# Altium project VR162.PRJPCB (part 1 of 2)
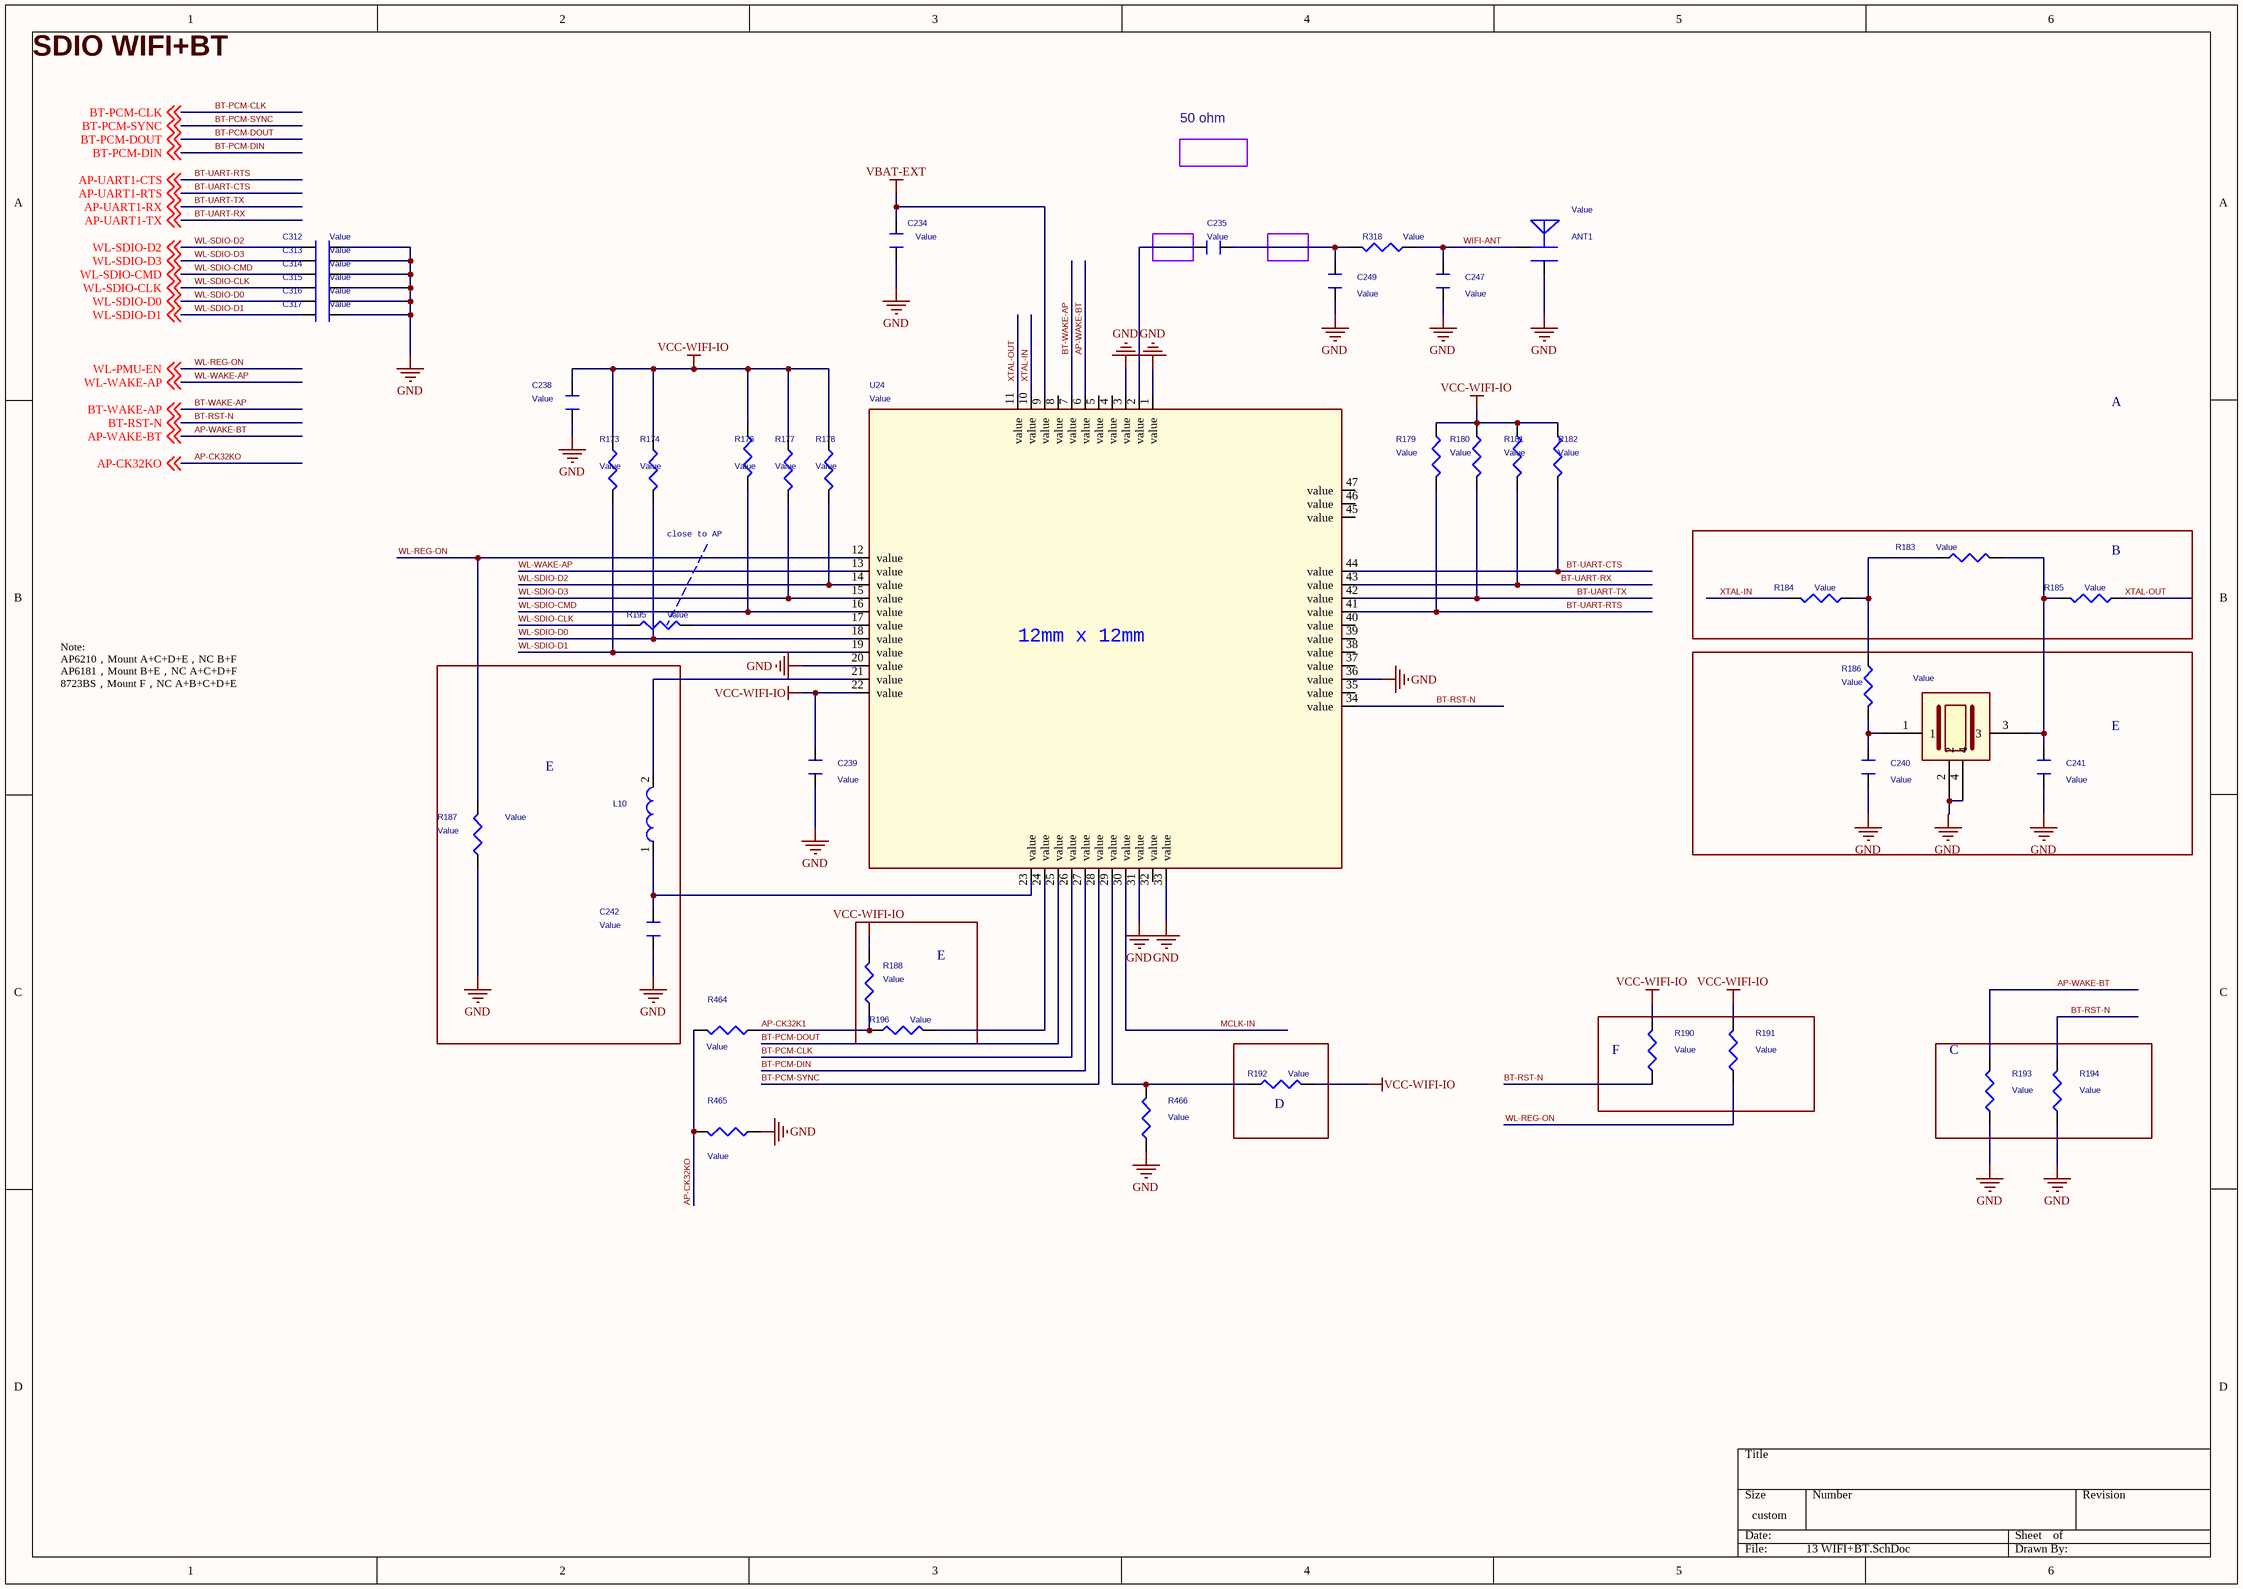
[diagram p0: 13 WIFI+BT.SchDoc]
12 sheets, 480 parts. Net scope: global (net labels, ports and power ports of the same name join across sheets).
Sheets:
  13 WIFI+BT.SchDoc
  12 CODEC.SchDoc
  11 CARD-SENSOR-VIBRATOR.SchDoc
  10 MIPI DSI.SchDoc
  08 NAND-eMMC.SchDoc
  07 POWER.SchDoc
  06 CPU.SchDoc
  05 LPDDR3_32X1.SchDoc
  03 POWER TREE.SchDoc
  14 TP.SchDoc
  09 CAMERA.SchDoc
  15 SENSOR.SchDoc

## Sheet 13 WIFI+BT.SchDoc
size 420 x 297 mm

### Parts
ANT1  Value  [CON2-WIFI-PT4]
C234  Value  [C0603]
C235  Value  [C0402]
C238  Value  [C0402]
C239  Value  [C0603]
C240  Value  [C0402]
C241  Value  [C0402]
C242  Value  [C0603]
C247  Value  [C0402]
C249  Value  [C0402]
C312  Value  [C0402]
C313  Value  [C0402]
C314  Value  [C0402]
C315  Value  [C0402]
C316  Value  [C0402]
C317  Value  [C0402]
L10  Value  [L3518]
R173  Value  [R0402]
R174  Value  [R0402]
R176  Value  [R0402]
R177  Value  [R0402]
R178  Value  [R0402]
R179  Value  [R0402]
R180  Value  [R0402]
R181  Value  [R0402]
R182  Value  [R0402]
R183  Value  [R0402]
R184  Value  [R0402]
R185  Value  [R0402]
R186  Value  [R0402]
R187  Value  [R0402]
R188  Value  [R0402]
R190  Value  [R0402]
R191  Value  [R0402]
R192  Value  [R0402]
R193  Value  [R0402]
R194  Value  [R0402]
R195  Value  [R0402]
R196  Value  [R0402]
R318  Value  [R0402]
R464  Value  [R0402]
R465  Value  [R0402]
R466  Value  [R0402]
U24  Value  [QFN44P0_90B12_00X12_00H1_50]
Y1  Value  [XTAL-1.6X1.2]

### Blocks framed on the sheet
B: R183-R185
E: C242 L10 R187
E: C240 C241 R186 Y1
E: R188 R196
D: R192
F: R190 R191
C: R193 R194

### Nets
GND: ANT1.2 C234.1 C238.1 C239.2 C240.2 C241.2 C242.2 C247.2 C249.2 C312.1 C313.1 C314.1 C315.1 C316.1 C317.1 R187.1 R193.1 R194.1 R465.1 R466.1 U24.1(value) U24.3(value) U24.20(value) U24.31(value) U24.33(value) U24.36(value) Y1.2 Y1.4
VBAT-EXT: C234.2 U24.9(value)  [project net BB-VBAT]
VCC-WIFI-IO: C238.2 C239.1 R173.1 R174.1 R176.1 R177.1 R178.1 R179.1 R180.1 R181.1 R182.1 R188.2 R190.2 R191.2 R192.2 U24.22(value)  [project net DLDO1]
AP-CK32K1: R188.1 R196.1 R464.1
AP-CK32KO: R464.2 R465.2 ; off-sheet AP-CK32KO
AP-WAKE-BT: R193.2 U24.6(value) ; off-sheet AP-WAKE-BT
BT-PCM-CLK: U24.26(value) ; off-sheet BT-PCM-CLK
BT-PCM-DIN: U24.27(value) ; off-sheet BT-PCM-DIN
BT-PCM-DOUT: U24.25(value) ; off-sheet BT-PCM-DOUT
BT-PCM-SYNC: U24.28(value) ; off-sheet BT-PCM-SYNC
BT-RST-N: R190.1 R194.2 U24.34(value) ; off-sheet BT-RST-N
BT-UART-CTS: R182.2 U24.44(value) ; off-sheet AP-UART1-RTS  [also labelled AP-UART1-RTS]
BT-UART-RTS: R179.2 U24.41(value) ; off-sheet AP-UART1-CTS  [also labelled AP-UART1-CTS]
BT-UART-RX: R181.2 U24.43(value) ; off-sheet AP-UART1-TX  [also labelled AP-UART1-TX]
BT-UART-TX: R180.2 U24.42(value) ; off-sheet AP-UART1-RX  [also labelled AP-UART1-RX]
BT-WAKE-AP: U24.7(value) ; off-sheet BT-WAKE-AP
MCLK-IN: U24.30(value)
WIFI-ANT: ANT1.1 C247.1 R318.1
WL-REG-ON: R187.2 R191.1 U24.12(value) ; off-sheet WL-PMU-EN  [also labelled WL-PMU-EN]
WL-SDIO-CLK: C315.2 R195.1 ; off-sheet WL-SDIO-CLK
WL-SDIO-CMD: C314.2 R176.2 U24.16(value) ; off-sheet WL-SDIO-CMD
WL-SDIO-D0: C316.2 R174.2 U24.18(value) ; off-sheet WL-SDIO-D0
WL-SDIO-D1: C317.2 R173.2 U24.19(value) ; off-sheet WL-SDIO-D1
WL-SDIO-D2: C312.2 R178.2 U24.14(value) ; off-sheet WL-SDIO-D2
WL-SDIO-D3: C313.2 R177.2 U24.15(value) ; off-sheet WL-SDIO-D3
WL-WAKE-AP: U24.13(value) ; off-sheet WL-WAKE-AP
XTAL-IN: R184.2 U24.10(value)
XTAL-OUT: R185.1 U24.11(value)
NetC235_1: C235.1 C249.1 R318.2
NetC235_2: C235.2 U24.2(value)
NetC240_1: C240.1 R186.2 Y1.1
NetC241_1: C241.1 R183.2 R185.2 Y1.3
NetC242_1: C242.1 L10.1 U24.23(value)
NetL10_2: L10.2 U24.21(value)
NetR183_1: R183.1 R184.1 R186.1
NetR192_1: R192.1 R466.2 U24.29(value)
NetR195_2: R195.2 U24.17(value)
NetR196_2: R196.2 U24.24(value)

Not connected (* = marked no-connect by the designer): U24 4(value) 5(value) 8(value) 32(value) 35(value) 37(value) 38(value) 39(value) 40(value) 45(value) 46(value) 47(value)

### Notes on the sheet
- SDIO WIFI+BT
- 50 ohm
- A
- close to AP
- Note:
  AP6210，Mount A+C+D+E，NC B+F
  AP6181，Mount B+E，NC A+C+D+F
  8723BS，Mount F，NC A+B+C+D+E

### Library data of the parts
ANT1 = T_POINT_R_0
C234 C235 C238-C242 C247 C249 C312-C317 = CAPACITOR_0_Dup3: PAGE: 2
L10 = INDUCTOR_Dup2
R173 R174 R176-R183 R186 R187 R190-R196 R318 R466 = R_Dup2
R184 R185 R188 R464 R465 = R_Dup1
U24 = AP6493_0: ORCAD_LIB: MODULE; QVL: AMPAK; Device: APSERIES
Y1 = Crystal_0

## Sheet 12 CODEC.SchDoc
size 420 x 297 mm
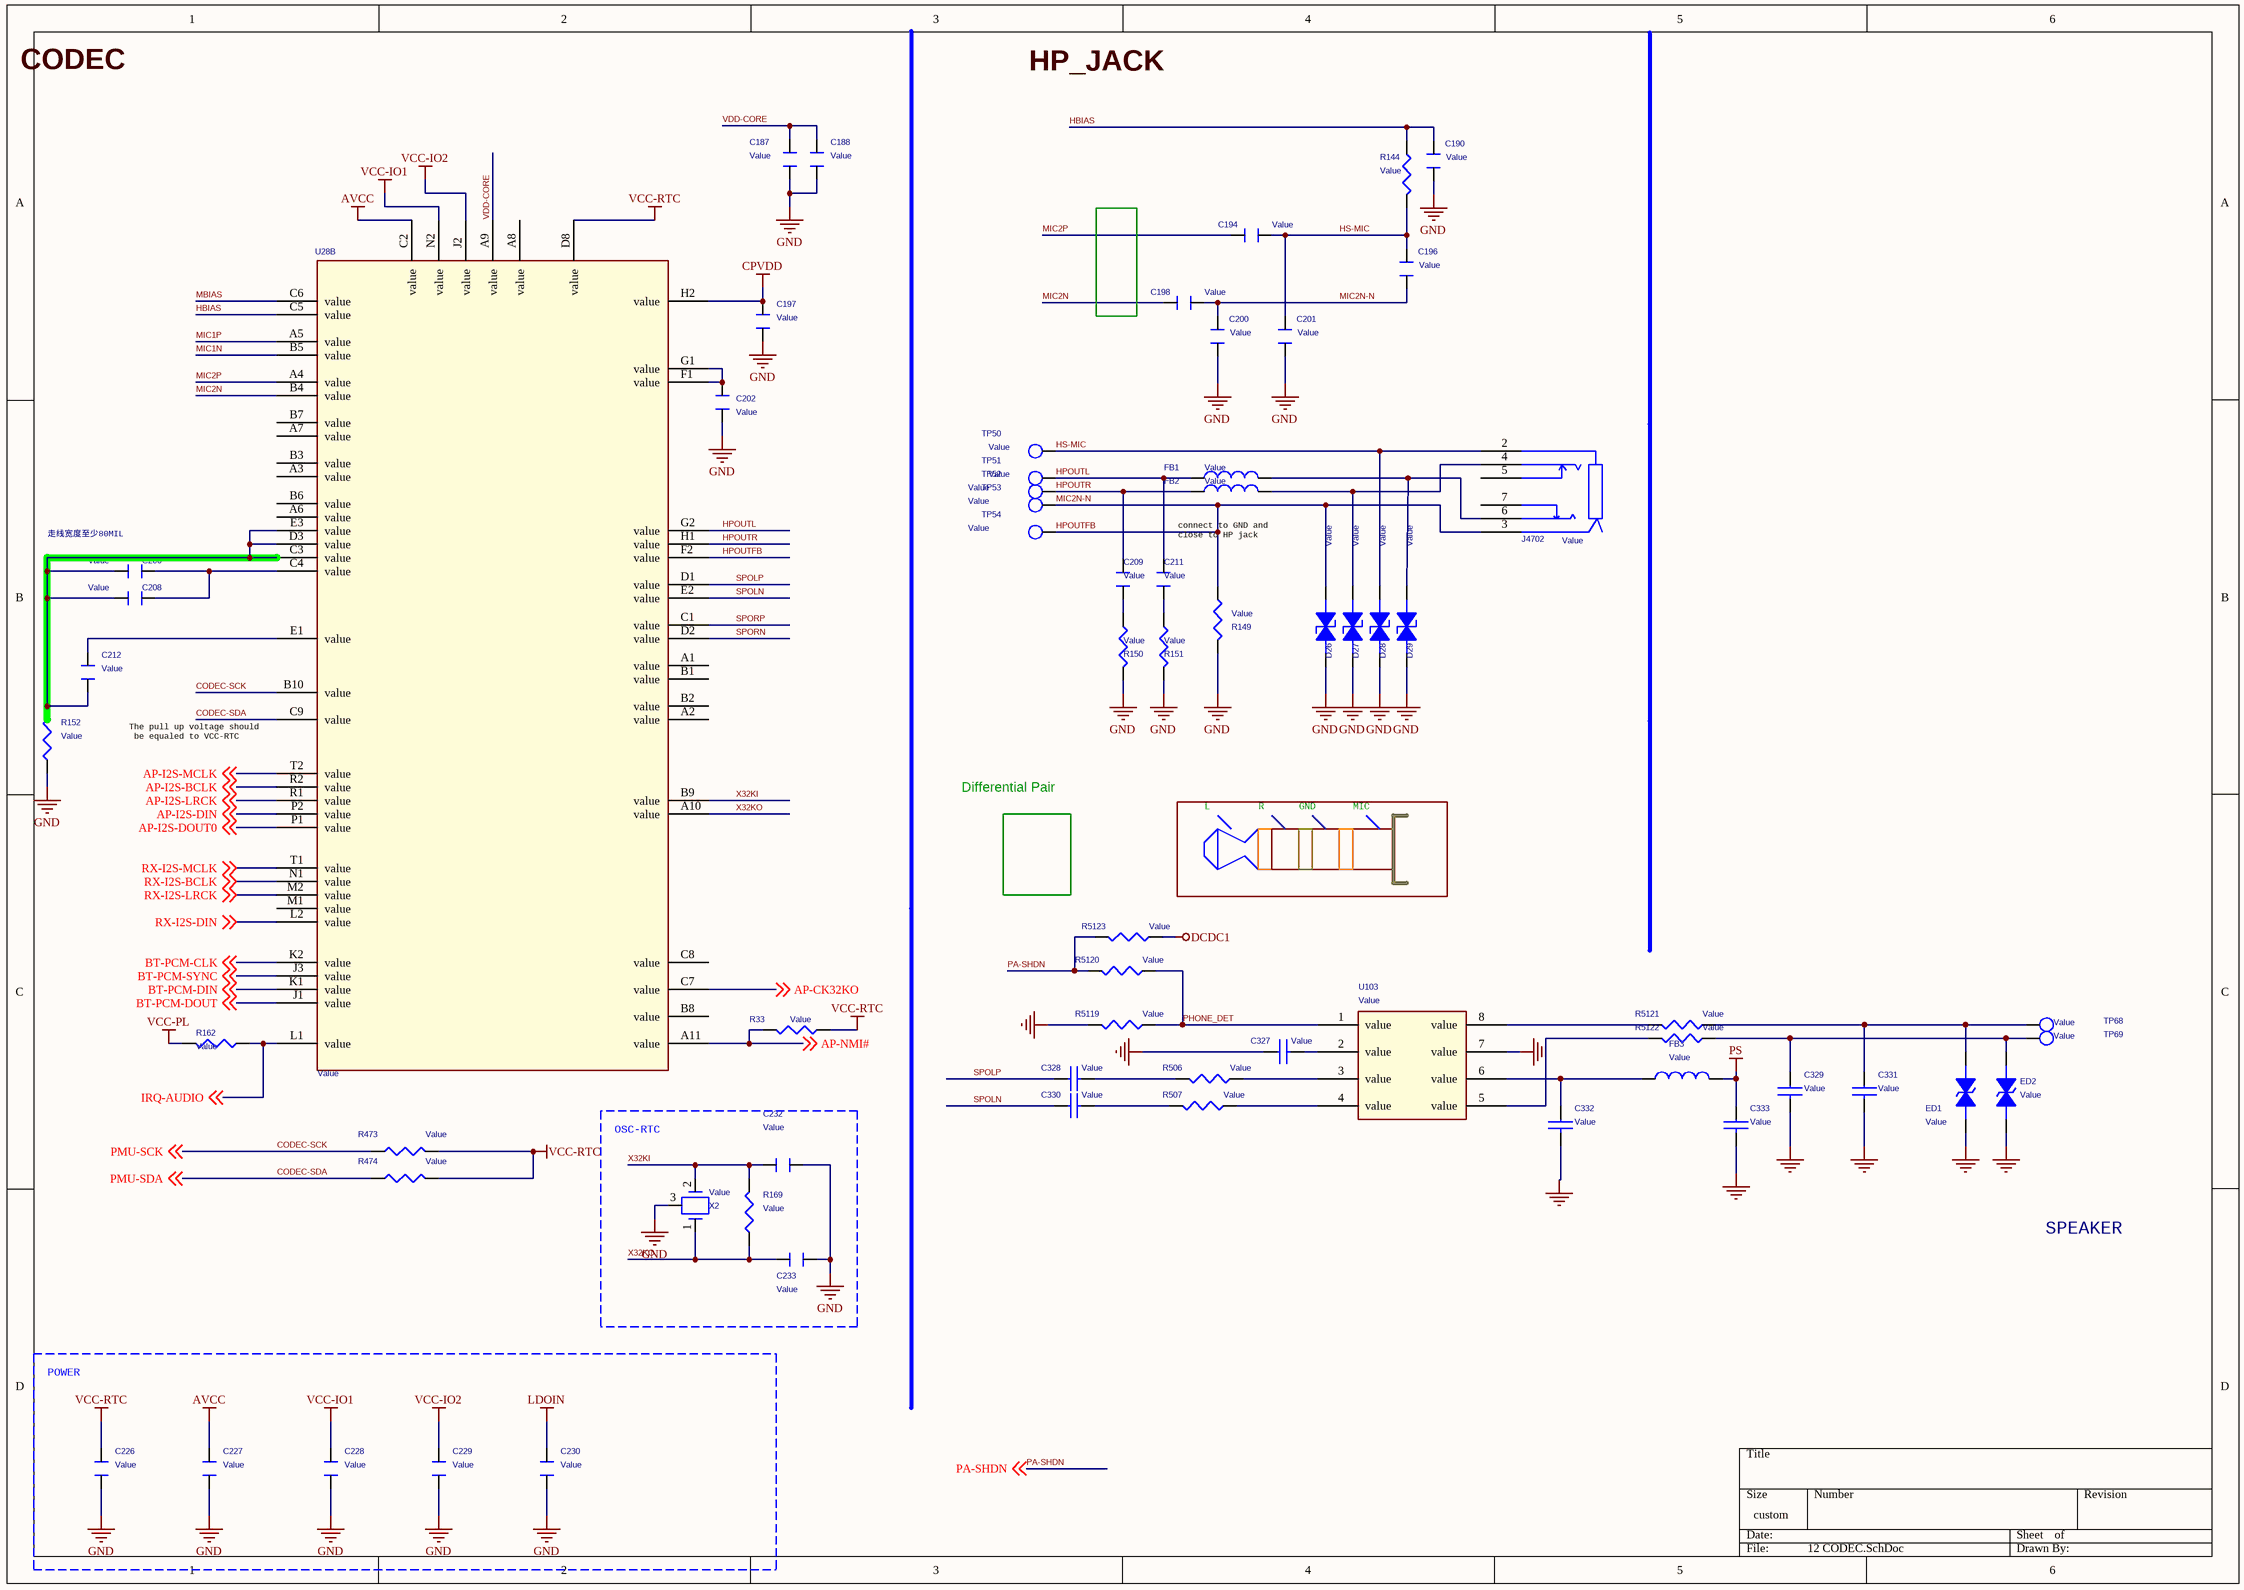
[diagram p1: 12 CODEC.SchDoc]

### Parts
C187  Value  [C0603]
C188  Value  [C0402]
C190  Value  [C0603]
C194  Value  [C0402]
C196  Value  [C0402]
C197  Value  [C0402]
C198  Value  [C0402]
C200  Value  [C0402]
C201  Value  [C0402]
C202  Value  [C0603]
C206  Value  [C0603]
C208  Value  [C0402]
C209  Value  [C0402]
C211  Value  [C0402]
C212  Value  [C0603]
C226  Value  [C0402]
C227  Value  [C0402]
C228  Value  [C0402]
C229  Value  [C0402]
C230  Value  [C0402]
C232  Value  [C0402]
C233  Value  [C0402]
C327  Value  [C0402]
C328  Value  [C0402]
C329  Value  [C0402]
C330  Value  [C0402]
C331  Value  [C0402]
C332  Value  [C0402]
C333  Value  [C0402]
D26  Value  [C0402]
D27  Value  [C0402]
D28  Value  [C0402]
D29  Value  [C0402]
ED1  Value  [E0402N]
ED2  Value  [E0402N]
FB1  Value  [L0402]
FB2  Value  [L0402]
FB3  Value  [L0603]
J4702  Value  [HP_JACK]
R33  Value  [R0402]
R144  Value  [R0402]
R149  Value  [0805]
R150  Value  [0805]
R151  Value  [0805]
R152  Value  [R0402]
R162  Value  [R0402]
R169  Value  [R0402]
R473  Value  [R0402]
R474  Value  [R0402]
R506  Value  [R0402]
R507  Value  [R0402]
R5119  Value  [R0402]
R5120  Value  [R0402]
R5121  Value  [R0402]
R5122  Value  [R0402]
R5123  Value  [R0402]
TP50  Value  [TP_SMD]
TP51  Value  [TP_SMD]
TP52  Value  [TP_SMD]
TP53  Value  [TP_SMD]
TP54  Value  [TP_SMD]
TP68  Value  [TP_SMD]
TP69  Value  [TP_SMD]
U28  Value  [BGA218_P0_65B11X11]  (part B of 4)
U103  Value  [MSOP8-PT1-27A]
X2  Value  [XCOL-3]

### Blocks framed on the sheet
OSC-RTC: C232 C233 R169 X2
POWER: C226-C230

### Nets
AVCC: C227.2 R162.2 U28.C2(value)  [also labelled VCC-PL]  [project net ALDO3]
CPVDD: C197.1 C230.2 U28.H2(value)  [also labelled LDOIN]  [project net ALDO2]
DCDC1: C228.2 R5123.1 U28.N2(value)  [also labelled VCC-IO1]
GND: C187.1 C188.1 C190.1 C197.2 C200.1 C201.1 C202.2 C226.1 C227.1 C228.1 C229.1 C230.1 C232.1 C233.1 C327.1 C329.2 C331.2 C332.2 C333.2 D26.2(CATHODE) D27.2(CATHODE) D28.2(CATHODE) D29.2(CATHODE) ED1.2 ED2.2 R149.1 R150.1 R151.1 R152.1 R5119.2 U103.7(value) X2.3(Shield)
PS: C333.1 FB3.1
VCC-IO2: C229.2 U28.J2(value)  [project net DLDO1]
VCC-RTC: C226.2 R33.1 R473.1 R474.1 U28.D8(value)
AP-CK32KO: U28.C7(value) ; off-sheet AP-CK32KO
AP-I2S-BCLK: U28.R2(value) ; off-sheet AP-I2S-BCLK
AP-I2S-DIN: U28.P2(value) ; off-sheet AP-I2S-DIN
AP-I2S-DOUT0: U28.P1(value) ; off-sheet AP-I2S-DOUT0
AP-I2S-LRCK: U28.R1(value) ; off-sheet AP-I2S-LRCK
AP-I2S-MCLK: U28.T2(value) ; off-sheet AP-I2S-MCLK
AP-NMI#: R33.2 U28.A11(value) ; off-sheet AP-NMI#
BT-PCM-CLK: U28.K2(value) ; off-sheet BT-PCM-CLK
BT-PCM-DIN: U28.K1(value) ; off-sheet BT-PCM-DIN
BT-PCM-DOUT: U28.J1(value) ; off-sheet BT-PCM-DOUT
BT-PCM-SYNC: U28.J3(value) ; off-sheet BT-PCM-SYNC
CODEC-SCK: R473.2 U28.B10(value) ; off-sheet PMU-SCK  [also labelled PMU-SCK]
CODEC-SDA: R474.2 U28.C9(value) ; off-sheet PMU-SDA  [also labelled PMU-SDA]
HBIAS: C190.2 R144.2 U28.C5(value)
HPOUTFB: C196.1 C198.2 C200.2 D26.1(ANODE) J4702.3 R149.2 TP53.1(TP) TP54.1(TP) U28.F2(value)  [also labelled MIC2N-N]
HPOUTL: C211.2 FB1.1 TP51.1(TP) U28.G2(value)
HPOUTR: C209.2 FB2.1 TP52.1(TP) U28.H1(value)
HS-MIC: C194.2 C196.2 C201.2 D28.1(ANODE) J4702.2(G) R144.1 TP50.1(TP)
IRQ-AUDIO: R162.1 U28.L1(value) ; off-sheet IRQ-AUDIO
MBIAS: U28.C6(value)
MIC1N: U28.B5(value)
MIC1P: U28.A5(value)
MIC2N: C198.1 U28.B4(value)
MIC2P: C194.1 U28.A4(value)
PA-SHDN: R5120.2 R5123.2 ; off-sheet PA-SHDN
PHONE_DET: R5119.1 R5120.1 U103.1(value)
RX-I2S-BCLK: U28.N1(value) ; off-sheet RX-I2S-BCLK
RX-I2S-DIN: U28.L2(value) ; off-sheet RX-I2S-DIN
RX-I2S-LRCK: U28.M2(value) ; off-sheet RX-I2S-LRCK
RX-I2S-MCLK: U28.T1(value) ; off-sheet RX-I2S-MCLK
SPOLN: C330.1 U28.E2(value)
SPOLP: C328.1 U28.D1(value)
SPORN: U28.D2(value)
SPORP: U28.C1(value)
VDD-CORE: C187.2 C188.2 U28.A9(value)
X32KI: C232.2 R169.2 U28.B9(value) X2.2
X32KO: C233.2 R169.1 U28.A10(value) X2.1
NetC202_1: C202.1 U28.F1(value) U28.G1(value)
NetC206_1: C206.1 C208.1 C212.2 R152.2 U28.C3(value) U28.D3(value) U28.E3(value)
NetC206_2: C206.2 C208.2 U28.C4(value)
NetC209_1: C209.1 R150.2
NetC211_1: C211.1 R151.2
NetC212_1: C212.1 U28.E1(value)
NetC327_2: C327.2 U103.2(value)
NetC328_2: C328.2 R506.2
NetC329_1: C329.1 ED2.1 R5122.1 TP69.1(TP)
NetC330_2: C330.2 R507.2
NetC331_1: C331.1 ED1.1 R5121.1 TP68.1(TP)
NetC332_1: C332.1 FB3.2 U103.6(value)
NetD27_1: D27.1(ANODE) FB2.2 J4702.4
NetD29_1: D29.1(ANODE) FB1.2 J4702.6
NetR506_1: R506.1 U103.3(value)
NetR507_1: R507.1 U103.4(value)
NetR5121_2: R5121.2 U103.8(value)
NetR5122_2: R5122.2 U103.5(value)

Not connected (* = marked no-connect by the designer): J4702 5 7; U28 A1(value) A2(value) A3(value) A6(value) A7(value) A8(value) B1(value) B2(value) B3(value) B6(value) B7(value) B8(value) C8(value) M1(value)

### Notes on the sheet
- CODEC
- HP_JACK
- connect to GND and
  close to HP jack
- 走线宽度至少80MIL
- (near U28) The pull up voltage should
  be equaled to VCC-RTC
- Differential Pair
- L
- R
- GND
- MIC
- SPEAKER

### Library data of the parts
C187 C232 C233 = CAPACITOR_0_Dup3: PAGE: 2
C188 C209 C211 C226-C230 = CAPACITOR_0_Dup3
C190 C194 C196 C198 C200 C201 = CAPACITOR: PAGE: 2
C197 C202 C206 C208 C212 = CAPACITOR_0_Dup2: PAGE: 1
C327 = CAP NP_Dup1: RoHS CHIP CAP 1uF +10/-10% X5R; BOM_VALUE: 0; BOM_TYPE: 30
C328 C329 C331 C333 = CAP NP_Dup1: RoHS CHIP CAP 0.1uF +10/-10% X7R; BOM_TYPE: 30; BOM_VALUE: 0
C330 = CAP NP_Dup1: RoHS CHIP CAP 0.1uF +10/-10% X7R; BOM_VALUE: 0; BOM_TYPE: 30
C332 = CAP NP_Dup1: RoHS CHIP CAP 10uF +10/-10% X5R; BOM_VALUE: 0; MARK: 106; ROOM: USB+5V; BOM_TYPE: 30
D26-D29 = 1_1.5KE100A: 1ST PART DESCRIPTION: WILL ESD9B5V Bidirection ESD Protection
ED1 ED2 = DIODE BI-DIR TRIG: NC/ESD Component,5V,30P,SMD,0402; BOM_TYPE: 43; BOM_VALUE: 0
FB1 FB2 = INDUCTOR_2
FB3 = INDUCTOR: ROHS CHIP RES 0 Ohm 1/16W +/-5%; BOM_TYPE: 20; BOM_VALUE: 0
J4702 = HP_JACK_0
R33 R152 R162 R169 = R_Dup1
R144 R473 R474 = R_Dup2
R149-R151 = R1 0805_Dup1
R506 = RESISTOR_Dup1: ROHS CHIP RES 30K 1/16W +/-5%; BOM_VALUE: 0; BOM_TYPE: 20
R507 R5121 R5122 = RESISTOR_Dup1: ROHS CHIP RES 62K 1/16W +/-5%; BOM_VALUE: 0; BOM_TYPE: 20
R5119 = RESISTOR_Dup1: ROHS CHIP RES 1M 1/16W +/-5%; BOM_TYPE: 20; BOM_VALUE: 0
R5120 R5123 = RESISTOR_Dup1: ROHS CHIP RES 100K 1/16W +/-5%
TP50-TP54 TP68 TP69 = T_POINT_R
U28 = AW1660_70_BGA218_1
U103 = LM4990_0: Class D Audio AMP; BOM_TYPE: 10; BOM_VALUE: 8
X2 = CRYSTAL_XCOL-3

## Sheet 11 CARD-SENSOR-VIBRATOR.SchDoc
size 420 x 297 mm
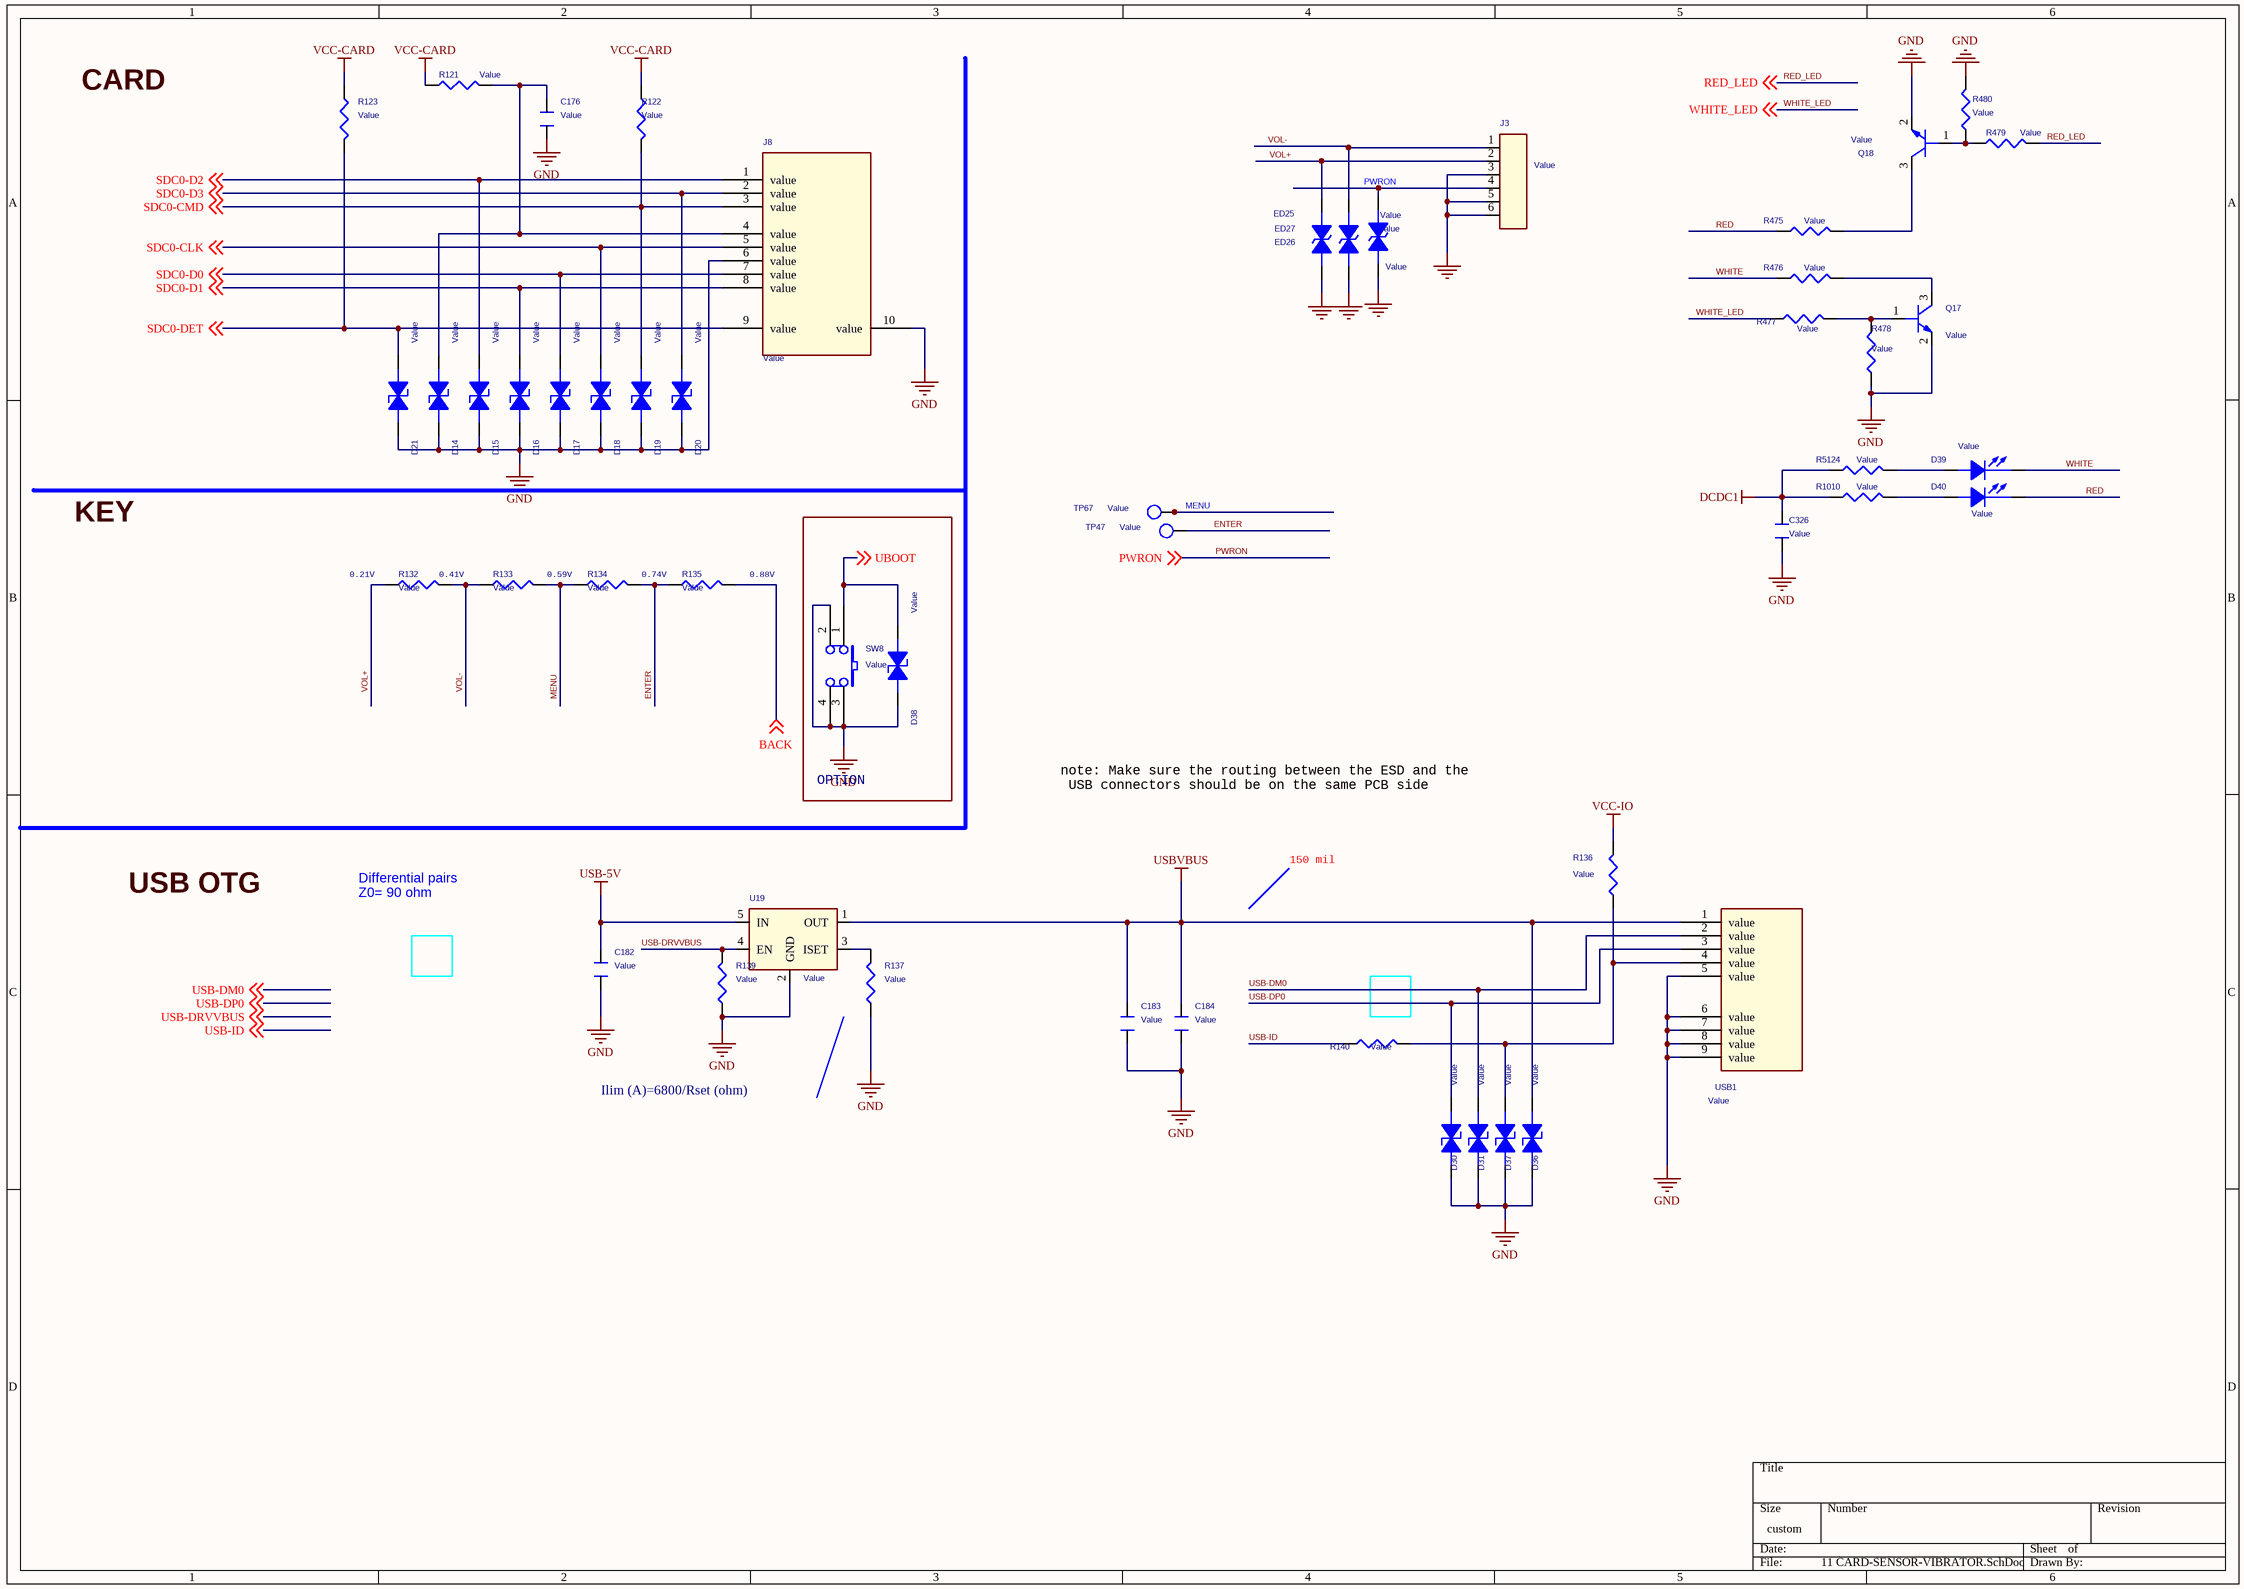
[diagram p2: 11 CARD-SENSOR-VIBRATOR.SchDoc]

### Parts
C176  Value  [C0603]
C182  Value  [C0402]
C183  Value  [C0402]
C184  Value  [C0603]
C326  Value  [C0402]
D14  Value  [C0402]
D15  Value  [C0402]
D16  Value  [C0402]
D17  Value  [C0402]
D18  Value  [C0402]
D19  Value  [C0402]
D20  Value  [C0402]
D21  Value  [C0402]
D30  Value  [C0402]
D31  Value  [C0402]
D36  Value  [C0402]
D37  Value  [C0402]
D38  Value  [C0402]
D39  Value  [LED0603]
D40  Value  [LED0603]
ED25  Value  [R0402]
ED26  Value  [R0402]
ED27  Value  [R0402]
J3  Value  [FPC4-PT1_25-3_8X10H4_6B]
J8  Value  [MICROSD_SLOT]
Q17  Value  [SOT-23]
Q18  Value  [SOT-23]
R121  Value  [R0603]
R122  Value  [R0402]
R123  Value  [R0402]
R132  Value  [0805]
R133  Value  [0805]
R134  Value  [0805]
R135  Value  [0805]
R136  Value  [R0402]
R137  Value  [R0402]
R139  Value  [R0402]
R140  Value  [R0402]
R475  Value  [R0402]
R476  Value  [R0402]
R477  Value  [R0402]
R478  Value  [R0402]
R479  Value  [R0402]
R480  Value  [R0402]
R1010  Value  [R0402]
R5124  Value  [R0402]
SW8  Value  [SW4]
TP47  Value  [TP_SMD]
TP67  Value  [TP_SMD]
U19  Value  [SOT23-6]
USB1  Value  [USB_MINI_AB]

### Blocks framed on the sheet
OPTION: D38 SW8

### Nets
DCDC1: C326.2 R121.1 R122.1 R123.1 R136.2 R1010.1 R5124.1  [also labelled VCC-CARD, VCC-IO]
GND: C176.1 C182.1 C183.1 C184.1 C326.1 D14.2(CATHODE) D15.2(CATHODE) D16.2(CATHODE) D17.2(CATHODE) D18.2(CATHODE) D19.2(CATHODE) D20.2(CATHODE) D21.2(CATHODE) D30.2(CATHODE) D31.2(CATHODE) D36.2(CATHODE) D37.2(CATHODE) D38.2(CATHODE) ED25.2 ED26.2 ED27.2 J3.3 J3.5 J3.6 J8.6(value) J8.10(value) Q17.2(E) Q18.2(E) R137.1 R139.1 R478.1 R480.2 SW8.2 SW8.3 SW8.4 U19.2(GND) USB1.5(value) USB1.6(value) USB1.7(value) USB1.8(value) USB1.9(value)
USB-5V: C182.2 U19.5(IN)
USBVBUS: C183.2 C184.2 D36.1(ANODE) U19.1(OUT) USB1.1(value)
BACK: R135.2 ; off-sheet BACK
ENTER: R134.2 R135.1 TP47.1(TP)
MENU: R133.2 R134.1 TP67.1(TP)
PWRON: ED25.1 J3.4 ; off-sheet PWRON
RED: D40.2(CATHODE) R475.1
RED_LED: R479.2 ; off-sheet RED_LED
SDC0-CLK: D18.1(ANODE) J8.5(value) ; off-sheet SDC0-CLK
SDC0-CMD: D19.1(ANODE) J8.3(value) R122.2 ; off-sheet SDC0-CMD
SDC0-D0: D17.1(ANODE) J8.7(value) ; off-sheet SDC0-D0
SDC0-D1: D16.1(ANODE) J8.8(value) ; off-sheet SDC0-D1
SDC0-D2: D15.1(ANODE) J8.1(value) ; off-sheet SDC0-D2
SDC0-D3: D20.1(ANODE) J8.2(value) ; off-sheet SDC0-D3
SDC0-DET: D21.1(ANODE) J8.9(value) R123.2 ; off-sheet SDC0-DET
UBOOT: D38.1(ANODE) SW8.1 ; off-sheet UBOOT
USB-DM0: D31.1(ANODE) USB1.2(value) ; off-sheet USB-DM0
USB-DP0: D30.1(ANODE) USB1.3(value) ; off-sheet USB-DP0
USB-DRVVBUS: R139.2 U19.4(EN) ; off-sheet USB-DRVVBUS
USB-ID: R140.1 ; off-sheet USB-ID
VOL+: ED27.1 J3.2 R132.1
VOL-: ED26.1 J3.1 R132.2 R133.1
WHITE: D39.2(CATHODE) R476.1
WHITE_LED: R477.1 ; off-sheet WHITE_LED
NetC176_2: C176.2 D14.1(ANODE) J8.4(value) R121.2
NetD37_1: D37.1(ANODE) R136.1 R140.2 USB1.4(value)
NetD39_1: D39.1(ANODE) R5124.2
NetD40_1: D40.1(ANODE) R1010.2
NetQ17_1: Q17.1(B) R477.2 R478.2
NetQ17_3: Q17.3(C) R476.2
NetQ18_1: Q18.1(B) R479.1 R480.1
NetQ18_3: Q18.3(C) R475.2
NetR137_2: R137.2 U19.3(ISET)

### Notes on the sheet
- CARD
- KEY
- (near R132) 0.21V
- (near R132) 0.41V
- 0.59V
- 0.74V
- (near R135) 0.88V
- note: Make sure the routing between the ESD and the
  USB connectors should be on the same PCB side
- Differential pairs
  Z0= 90 ohm
- 150 mil
- USB OTG
- Ilim (A)=6800/Rset (ohm)

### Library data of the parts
C176 = CAPACITOR_0_Dup3: PAGE: 2
C182-C184 C326 = CAPACITOR
D14-D21 D30 D31 D36-D38 = 1_1.5KE100A: as D26 on sheet 12 CODEC
D39 D40 = LED_0: PAGE: 1
ED25-ED27 = DIODE BI-DIR TRIG: ESD
J3 = CON2_2
J8 = SDMMC SLOT_0
Q17 Q18 = NPN
R121-R123 R140 R475-R480 R1010 R5124 = R_Dup2
R132-R135 = R1 0805_Dup2
R136 R137 R139 = R_Dup1
SW8 = SW_PUSH: SDTSourceLibName: C:\WIND95\TEMP\6200.LIB
TP47 TP67 = T_POINT_R
U19 = RT9266PE_2
USB1 = USB_MINI_SOCKET_5: USB JACK ROHS

## Sheet 10 MIPI DSI.SchDoc
size 449 x 350 mm
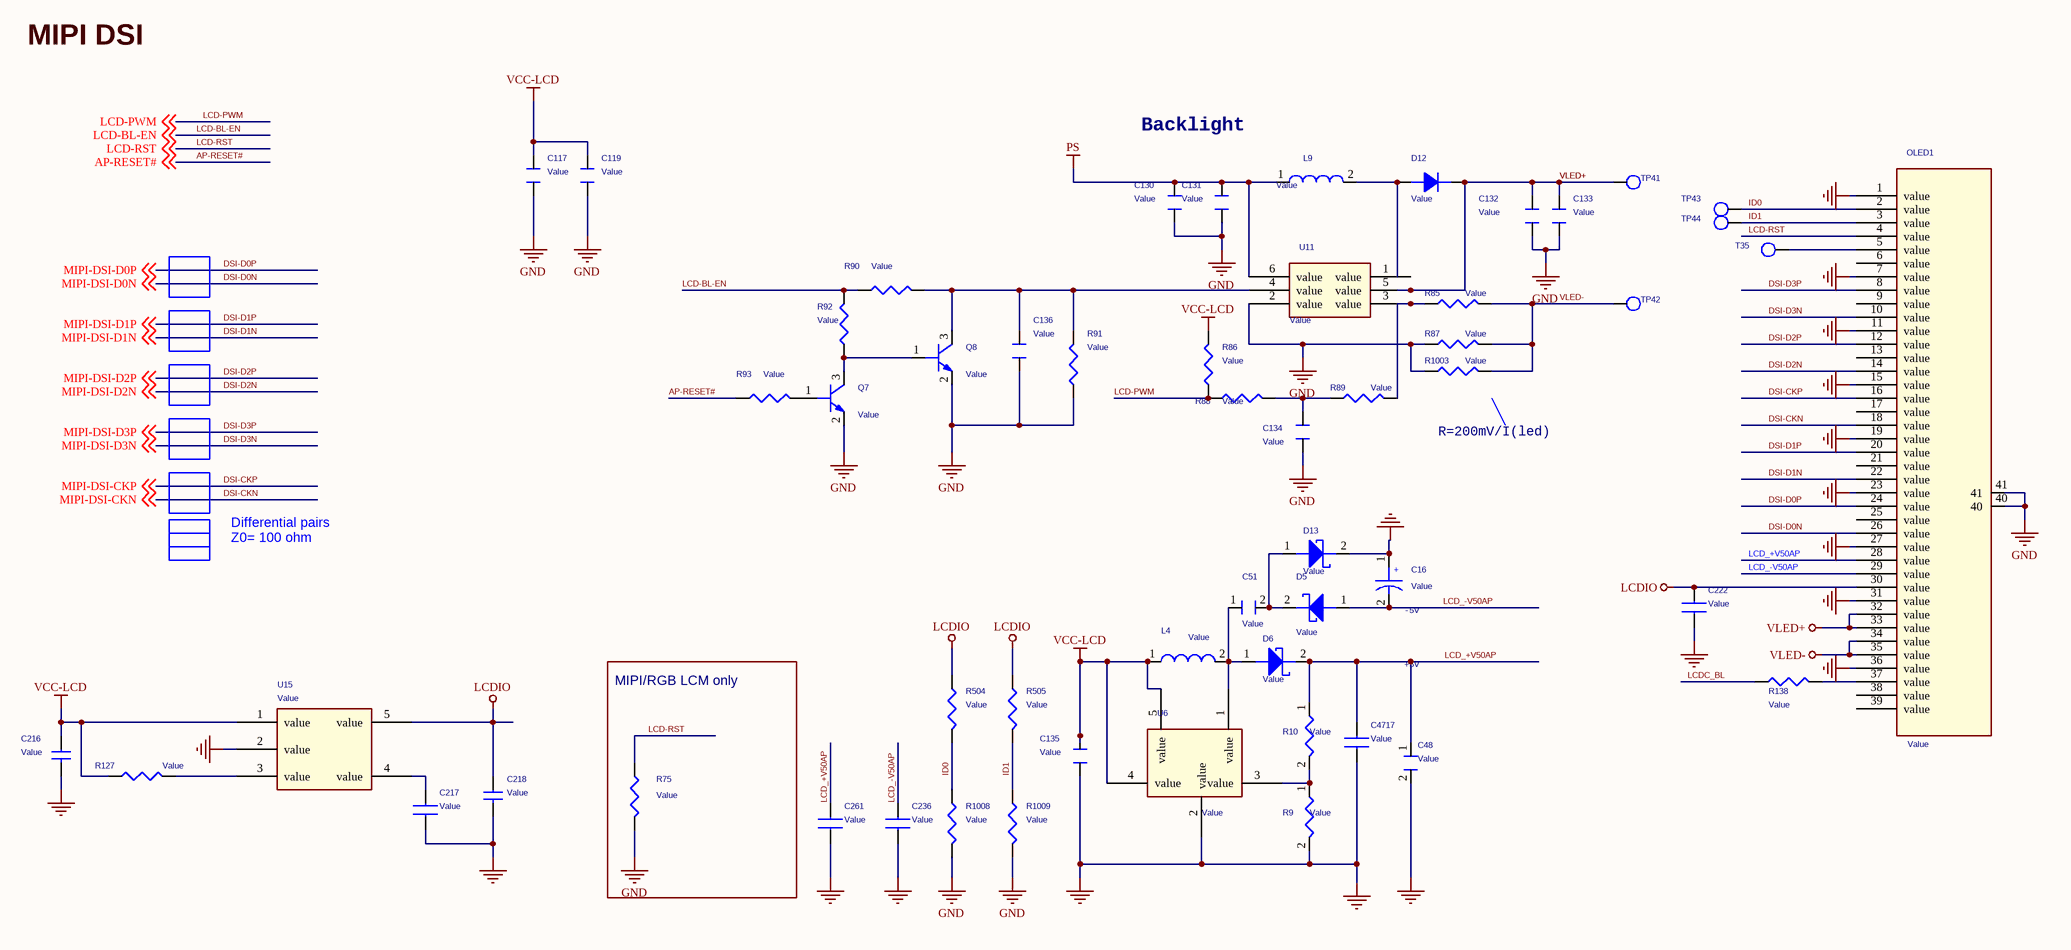
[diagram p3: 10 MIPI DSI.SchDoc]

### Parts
C16  Value  [1210]
C48  Value  [C0603]
C51  Value  [C0603]
C117  Value  [C0603]
C119  Value  [C0402]
C130  Value  [C0603]
C131  Value  [C0402]
C132  Value  [C0805]
C133  Value  [C0402]
C134  Value  [C0402]
C135  Value  [C0603]
C136  Value  [C0402]
C216  Value  [C0603]
C217  Value  [C0603]
C218  Value  [C0603]
C222  Value  [C0603]
C236  Value  [C0603]
C261  Value  [C0603]
C4717  Value  [C0603]
D5  Value  [SOD123]
D6  Value  [SOD123]
D12  Value  [SOD123]
D13  Value  [SOD123]
L4  Value  [CD32]
L9  Value  [L4018]
OLED1  Value  [40P_MIPI]
Q7  Value  [SOT-23]
Q8  Value  [SOT-23]
R9  Value  [0805]
R10  Value  [0805]
R75  Value  [R0402]
R85  Value  [R0402]
R86  Value  [R0402]
R87  Value  [R0603]
R88  Value  [R0402]
R89  Value  [R0402]
R90  Value  [R0402]
R91  Value  [R0402]
R92  Value  [R0402]
R93  Value  [R0402]
R127  Value  [R0402]
R138  Value  [R0402]
R504  Value  [R0402]
R505  Value  [R0402]
R1003  Value  [R0603]
R1008  Value  [R0402]
R1009  Value  [R0402]
T35  Value  [TEST]  (value not drawn)
TP41  Value  [TP_SMD]  (value not drawn)
TP42  Value  [TP_SMD]  (value not drawn)
TP43  Value  [TP_SMD]  (value not drawn)
TP44  Value  [TP_SMD]  (value not drawn)
U6  Value  [sot23-5]
U11  Value  [SOT23-6]
U15  Value  [SOT23_5H14A]

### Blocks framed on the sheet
MIPI/RGB LCM only: R75

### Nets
GND: C16.1 C48.2 C117.1 C119.1 C130.1 C131.1 C132.1 C133.1 C134.1 C135.1 C136.1 C216.2 C217.2 C218.2 C222.2 C236.2 C261.2 C4717.2 D13.2 OLED1.1(value) OLED1.7(value) OLED1.11(value) OLED1.15(value) OLED1.19(value) OLED1.23(value) OLED1.27(value) OLED1.31(value) OLED1.36(value) OLED1.40 OLED1.41 Q7.2(E) Q8.2(E) R9.2 R75.2 R87.2 R91.1 R1003.2 R1008.2 R1009.2 U6.2(value) U11.2(value) U15.2(value)
LCDIO: C218.1 C222.1 OLED1.30(value) R504.1 R505.1 U15.5(value)
PS: C130.2 C131.2 L9.1 U11.6(value)
VCC-LCD: C117.2 C119.2 C135.2 C216.1 L4.1 R86.2 R127.1 U6.4(value) U6.5(value) U15.1(value)  [project net DC1-SW]
VLED+: C132.2 C133.2 D12.2 OLED1.32(value) OLED1.33(value) TP41.1(TP) U11.5(value)
VLED-: OLED1.34(value) OLED1.35(value) R85.2 R87.1 R1003.1 TP42.1(TP)
AP-RESET#: R93.1 ; off-sheet AP-RESET#
DSI-CKN: OLED1.18(value) ; off-sheet MIPI-DSI-CKN  [also labelled MIPI-DSI-CKN]
DSI-CKP: OLED1.16(value) ; off-sheet MIPI-DSI-CKP  [also labelled MIPI-DSI-CKP]
DSI-D0N: OLED1.26(value) ; off-sheet MIPI-DSI-D0N  [also labelled MIPI-DSI-D0N]
DSI-D0P: OLED1.24(value) ; off-sheet MIPI-DSI-D0P  [also labelled MIPI-DSI-D0P]
DSI-D1N: OLED1.22(value) ; off-sheet MIPI-DSI-D1N  [also labelled MIPI-DSI-D1N]
DSI-D1P: OLED1.20(value) ; off-sheet MIPI-DSI-D1P  [also labelled MIPI-DSI-D1P]
DSI-D2N: OLED1.14(value) ; off-sheet MIPI-DSI-D2N  [also labelled MIPI-DSI-D2N]
DSI-D2P: OLED1.12(value) ; off-sheet MIPI-DSI-D2P  [also labelled MIPI-DSI-D2P]
DSI-D3N: OLED1.10(value) ; off-sheet MIPI-DSI-D3N  [also labelled MIPI-DSI-D3N]
DSI-D3P: OLED1.8(value) ; off-sheet MIPI-DSI-D3P  [also labelled MIPI-DSI-D3P]
ID0: OLED1.2(value) R504.2 R1008.1 TP43.1(TP)
ID1: OLED1.3(value) R505.2 R1009.1 TP44.1(TP)
LCD-BL-EN: R90.1 R92.2 ; off-sheet LCD-BL-EN
LCD-PWM: R86.1 R88.1 ; off-sheet LCD-PWM
LCD-RST: OLED1.4(value) R75.1 ; off-sheet LCD-RST
LCD_+V50AP: C48.1 C261.1 C4717.1 D6.2 OLED1.28(value) R10.1
LCD_-V50AP: C16.2 C236.1 D5.1 OLED1.29(value)
LCDC_BL: R138.1
NetC51_1: C51.1 D6.1 L4.2 U6.1(value)
NetC51_2: C51.2 D5.2 D13.1
NetC134_2: C134.2 R88.2 R89.1
NetC136_2: C136.2 Q8.3(C) R90.2 R91.2 U11.4(value)
NetC217_1: C217.1 U15.4(value)
NetD12_1: D12.1 L9.2
NetOLED1_5: OLED1.5(value) T35.1
NetOLED1_37: OLED1.37(value) R138.2
NetQ7_1: Q7.1(B) R93.2
NetQ7_3: Q7.3(C) Q8.1(B) R92.1
NetR9_1: R9.1 R10.2 U6.3(value)
NetR85_1: R85.1 R89.2 U11.3(value)
NetR127_2: R127.2 U15.3(value)

Not connected (* = marked no-connect by the designer): OLED1 6(value) 9(value) 13(value) 17(value) 21(value) 25(value) 38(value) 39(value); U11 1(value)

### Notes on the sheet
- MIPI DSI
- Backlight
- R=200mV/I(led)
- Differential pairs
  Z0= 100 ohm
- (near C16) -5v
- +5v

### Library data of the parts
C16 = CAP_P_1210
C48 C51 = CAPACITOR_3: PAGE: 3
C117 C119 C130-C136 = CAPACITOR_0: PAGE: 2
C216 C218 = SMALL CAP: 贴片电容
C217 C222 C236 C261 C4717 = CAP NP
D5 D6 D13 = DIODE SCHOTTKY_0: PAGE: 3
D12 = D_0: Allegro PCB Footprint: d2513A
L4 = INDUCTOR_Dup1: PAGE: 3
L9 = INDUCTOR_Dup3: RoHS Power Inductor 22uH 300mA H<1.8MM,CD32
OLED1 = 40P_MIPI_0
Q7 Q8 = NPN
R9 R10 = RESISTOR_3: PAGE: 3
R75 R85-R93 R504 R505 R1003 R1008 R1009 = RESISTOR_Dup2
R127 R138 = RES 1B_Dup1: ROHS CHIP RES 4.7K 1/16W 5%
T35 = TESTPOINT1: TEST
TP41-TP44 = T_POINT_R
U6 = SP6646_0: PAGE: 3
U11 = AP3031_0
U15 = LDO-PT5108/RT9013_0

## Sheet 08 NAND-eMMC.SchDoc
size 420 x 297 mm
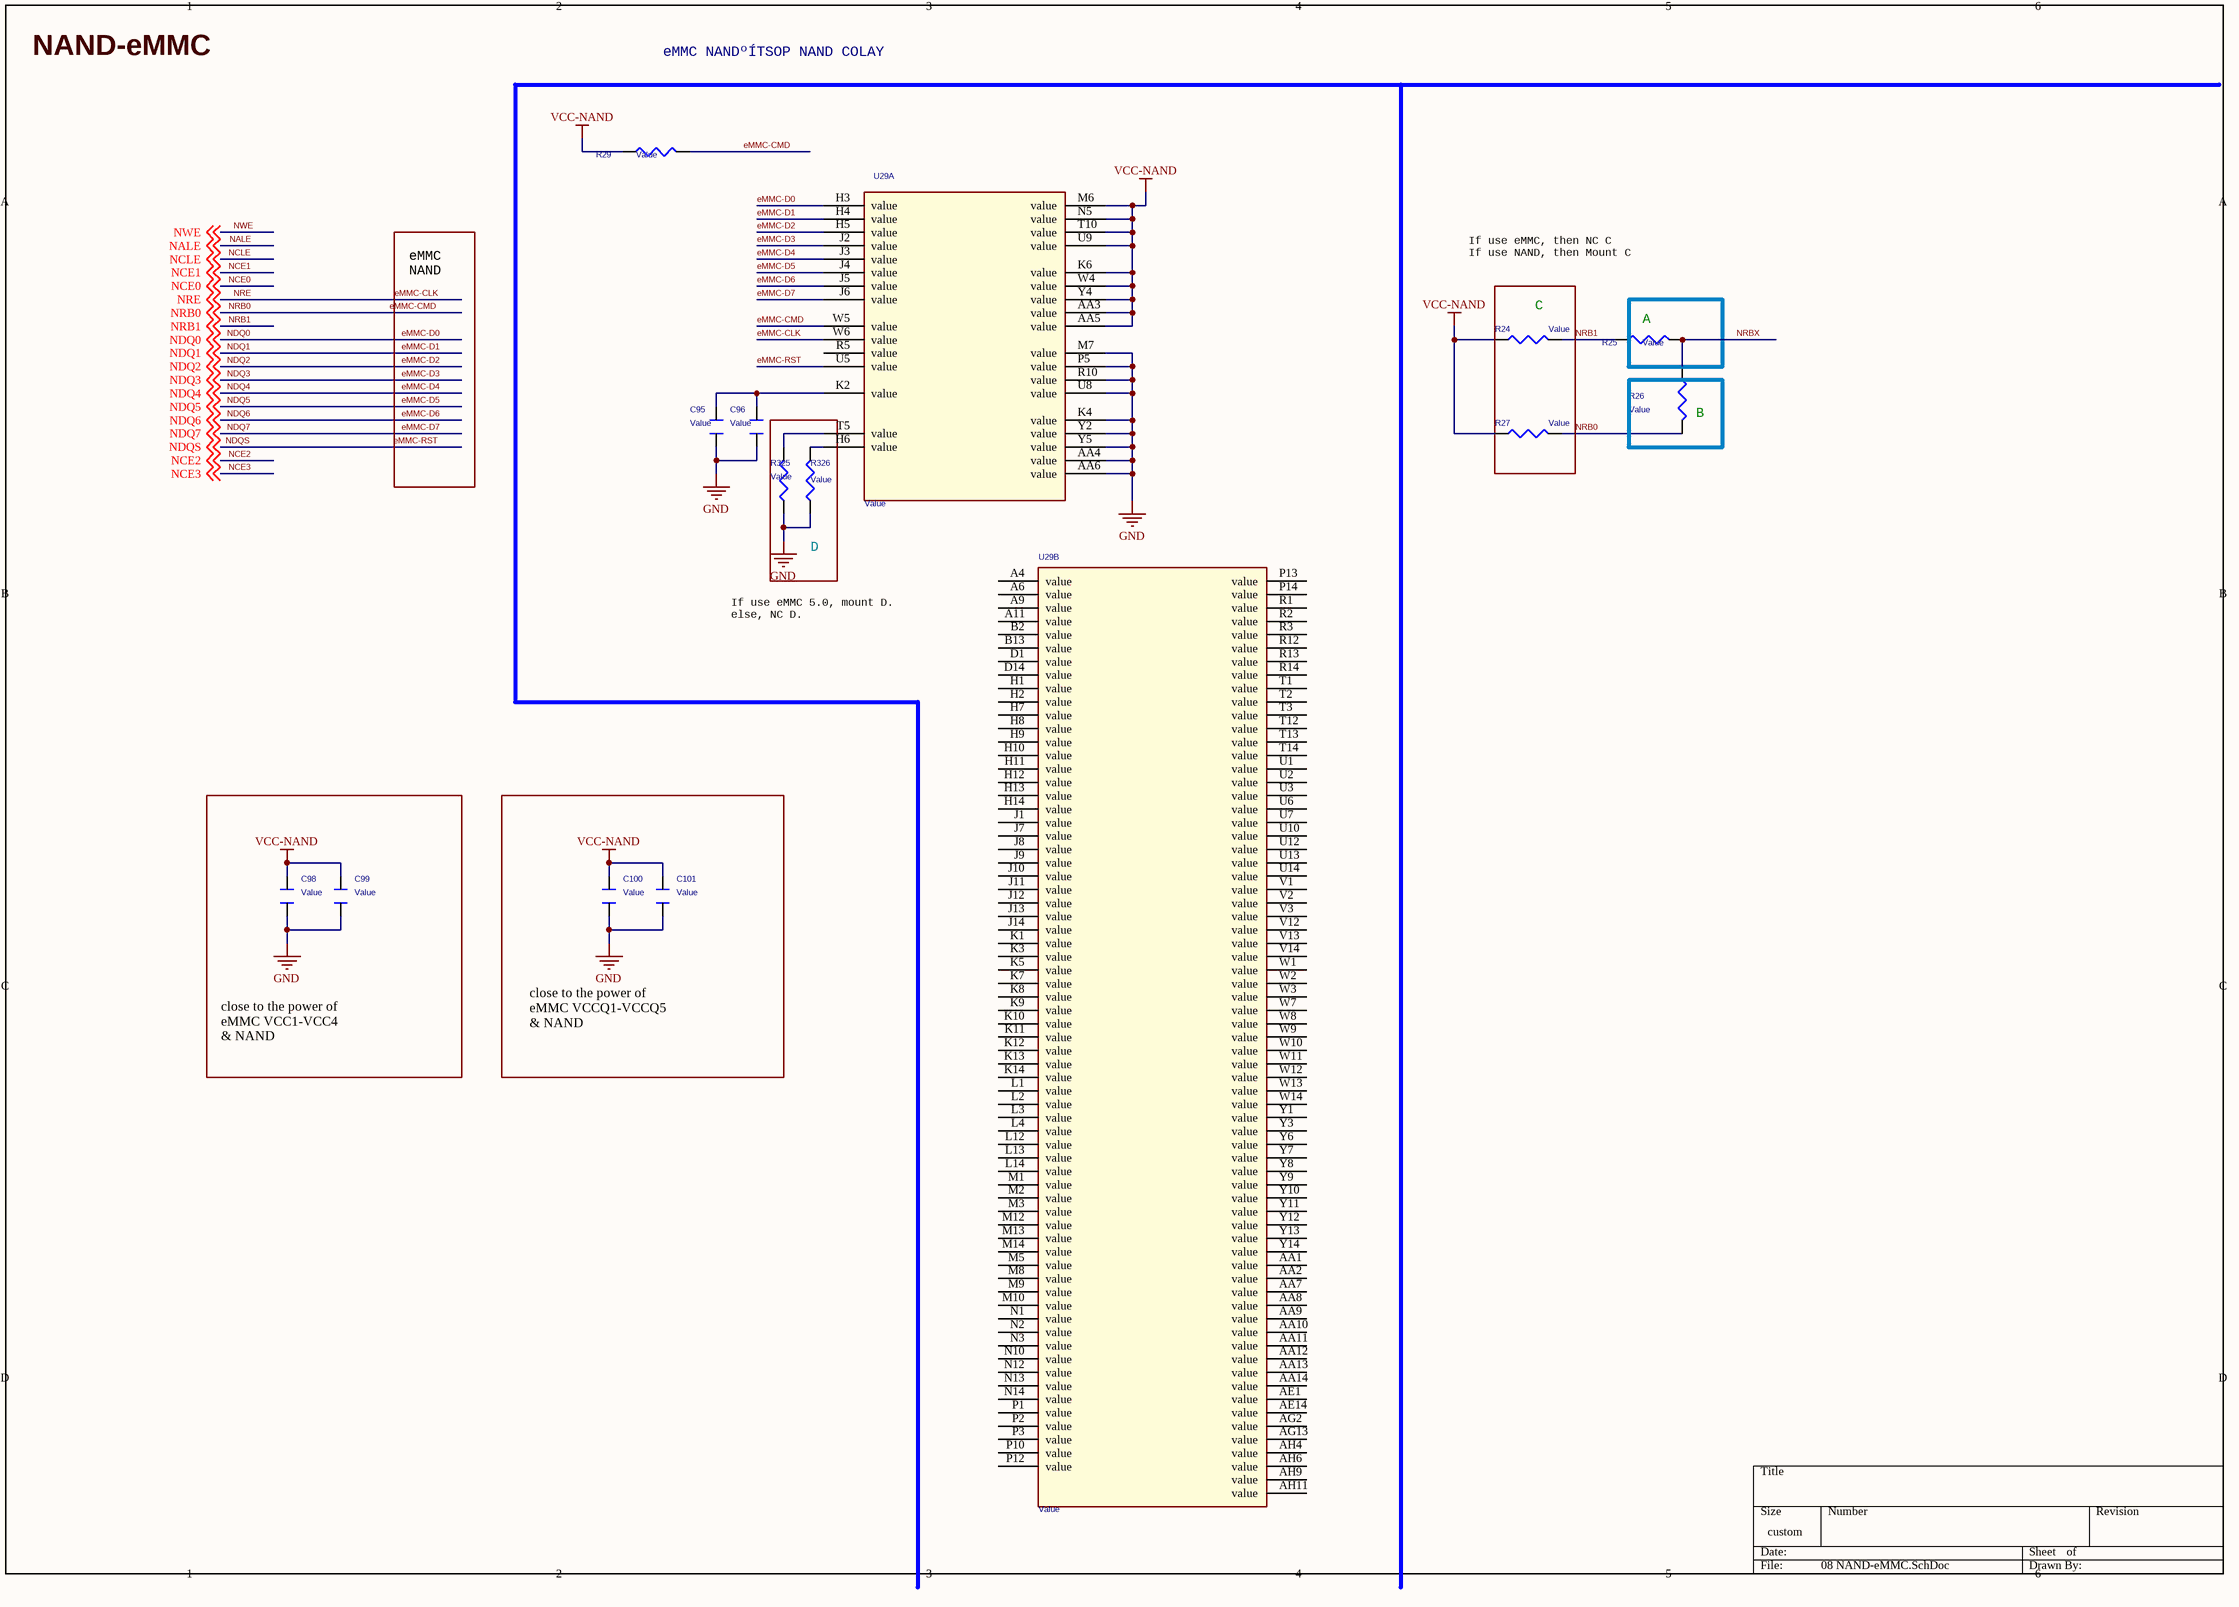
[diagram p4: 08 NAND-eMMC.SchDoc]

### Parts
C95  Value  [C0402]
C96  Value  [C0402]
C98  Value  [C0402]
C99  Value  [C0402]
C100  Value  [C0402]
C101  Value  [C0402]
R24  Value  [R0402]
R25  Value  [R0402]
R26  Value  [R0402]
R27  Value  [R0402]
R29  Value  [R0402]
R325  Value  [R0402]
R326  Value  [R0402]
U29  Value  [BGA169P0_50B12_00X16_00H1_00]  (parts A,B of 2)

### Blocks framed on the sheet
C: R24 R27
A: R25
D: R325 R326
B: R26

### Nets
GND: C95.1 C96.1 C98.1 C99.1 C100.1 C101.1 R325.1 R326.1 U29.AA4(value) U29.AA6(value) U29.K4(value) U29.M7(value) U29.P5(value) U29.R10(value) U29.U8(value) U29.Y2(value) U29.Y5(value)
VCC-NAND: C98.2 C99.2 C100.2 C101.2 R24.1 R27.1 R29.1 U29.AA3(value) U29.AA5(value) U29.K6(value) U29.M6(value) U29.N5(value) U29.T10(value) U29.U9(value) U29.W4(value) U29.Y4(value)  [project net DCDC1]
eMMC-CLK: U29.W6(value) ; off-sheet NRE  [also labelled NRE]
eMMC-CMD: R26.2 R27.2 R29.2 U29.W5(value) ; off-sheet NRB0  [also labelled NRB0]
eMMC-D0: U29.H3(value) ; off-sheet NDQ0  [also labelled NDQ0]
eMMC-D1: U29.H4(value) ; off-sheet NDQ1  [also labelled NDQ1]
eMMC-D2: U29.H5(value) ; off-sheet NDQ2  [also labelled NDQ2]
eMMC-D3: U29.J2(value) ; off-sheet NDQ3  [also labelled NDQ3]
eMMC-D4: U29.J3(value) ; off-sheet NDQ4  [also labelled NDQ4]
eMMC-D5: U29.J4(value) ; off-sheet NDQ5  [also labelled NDQ5]
eMMC-D6: U29.J5(value) ; off-sheet NDQ6  [also labelled NDQ6]
eMMC-D7: U29.J6(value) ; off-sheet NDQ7  [also labelled NDQ7]
eMMC-RST: U29.U5(value) ; off-sheet NDQS  [also labelled NDQS]
NRB1: R24.2 R25.1 ; off-sheet NRB1
NRBX: R25.2 R26.1
NetC95_2: C95.2 C96.2 U29.K2(value)
NetR325_2: R325.2 U29.T5(value)
NetR326_2: R326.2 U29.H6(value)

Not connected (* = marked no-connect by the designer): U29 A4(value) A6(value) A9(value) A11(value) AA1(value) AA2(value) AA7(value) AA8(value) AA9(value) AA10(value) AA11(value) AA12(value) AA13(value) AA14(value) AE1(value) AE14(value) AG2(value) AG13(value) AH4(value) AH6(value) AH9(value) AH11(value) B2(value) B13(value) D1(value) D14(value) H1(value) H2(value) H7(value) H8(value) H9(value) H10(value) H11(value) H12(value) H13(value) H14(value) J1(value) J7(value) J8(value) J9(value) J10(value) J11(value) J12(value) J13(value) J14(value) K1(value) K3(value) K5(value) K7(value) K8(value) K9(value) K10(value) K11(value) K12(value) K13(value) K14(value) L1(value) L2(value) L3(value) L4(value) L12(value) L13(value) L14(value) M1(value) M2(value) M3(value) M5(value) M8(value) M9(value) M10(value) M12(value) M13(value) M14(value) N1(value) N2(value) N3(value) N10(value) N12(value) N13(value) N14(value) P1(value) P2(value) P3(value) P10(value) P12(value) P13(value) P14(value) R1(value) R2(value) R3(value) R5(value) R12(value) R13(value) R14(value) T1(value) T2(value) T3(value) T12(value) T13(value) T14(value) U1(value) U2(value) U3(value) U6(value) U7(value) U10(value) U12(value) U13(value) U14(value) V1(value) V2(value) V3(value) V12(value) V13(value) V14(value) W1(value) W2(value) W3(value) W7(value) W8(value) W9(value) W10(value) W11(value) W12(value) W13(value) W14(value) Y1(value) Y3(value) Y6(value) Y7(value) Y8(value) Y9(value) Y10(value) Y11(value) Y12(value) Y13(value) Y14(value)

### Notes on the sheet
- NAND-eMMC
- eMMC NANDºÍTSOP NAND COLAY
- eMMC
  NAND
- If use eMMC, then NC C
  If use NAND, then Mount C
- If use eMMC 5.0, mount D.
  else, NC D.
- close to the power of
  eMMC VCC1-VCC4
  & NAND
- close to the power of
  eMMC VCCQ1-VCCQ5
  & NAND

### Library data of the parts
C95 C98 C100 = CAPACITOR_0_Dup3: mypage: 08; PAGE: 2
C96 C99 C101 = CAPACITOR_0_Dup3: PAGE: 2; mypage: 08
R24 R27 R29 R325 R326 = R_Dup2: mypage: 08
R25 R26 = R_Dup1: mypage: 08
U29 = EMMC5_0_BGA169_0

## Sheet 07 POWER.SchDoc
size 420 x 297 mm
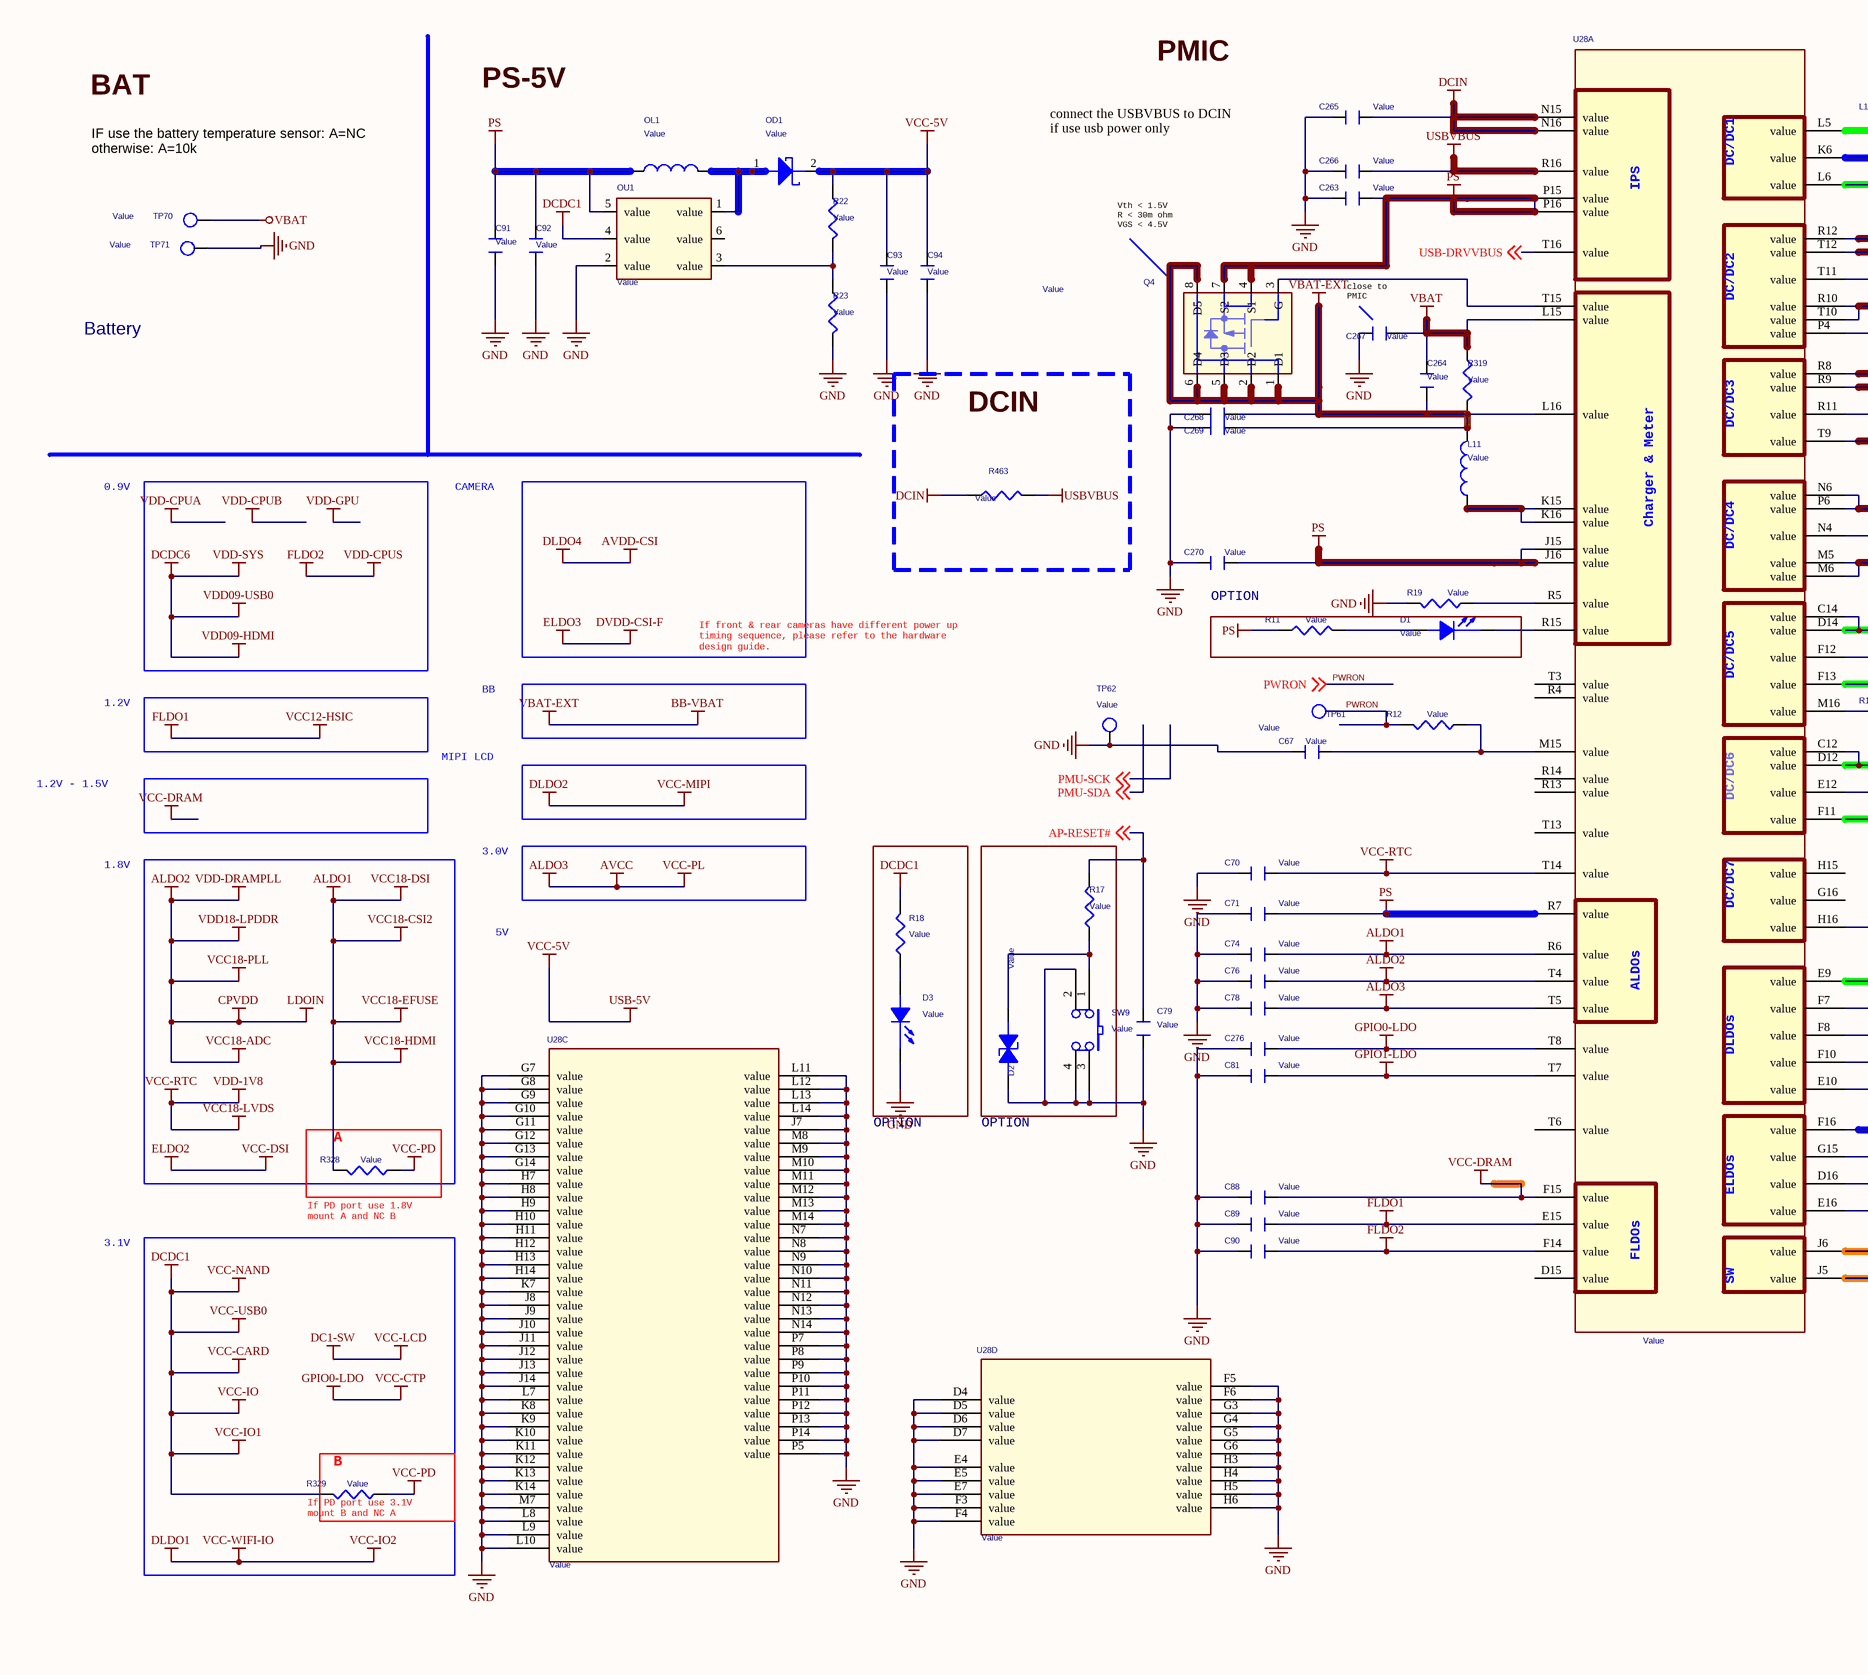
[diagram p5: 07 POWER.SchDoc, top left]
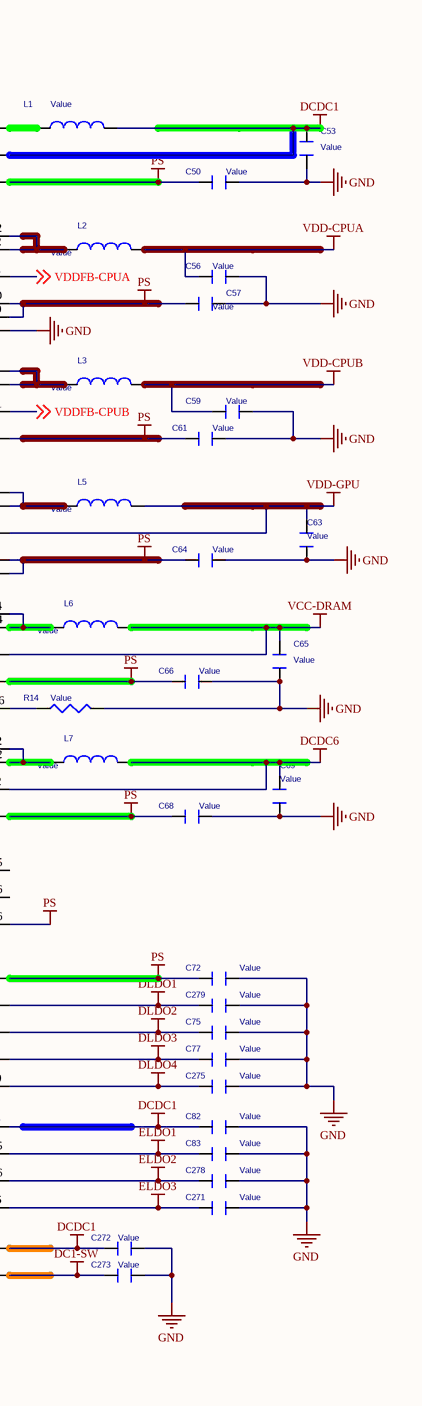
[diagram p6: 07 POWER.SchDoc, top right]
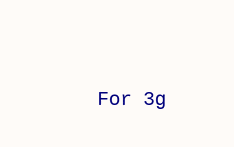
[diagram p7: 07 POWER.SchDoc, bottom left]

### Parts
C50  Value  [C0603]
C53  Value  [C0603]
C56  Value  [C0603]
C57  Value  [C0603]
C59  Value  [C0603]
C61  Value  [C0603]
C63  Value  [C0603]
C64  Value  [C0603]
C65  Value  [C0603]
C66  Value  [C0603]
C67  Value  [C0402]
C68  Value  [C0603]
C69  Value  [C0603]
C70  Value  [C0603]
C71  Value  [C0603]
C72  Value  [C0603]
C74  Value  [C0603]
C75  Value  [C0603]
C76  Value  [C0603]
C77  Value  [C0603]
C78  Value  [C0603]
C79  Value  [C0402]
C81  Value  [C0603]
C82  Value  [C0603]
C83  Value  [C0603]
C88  Value  [C0603]
C89  Value  [C0603]
C90  Value  [C0603]
C91  Value  [C0603]
C92  Value  [C0402]
C93  Value  [C0603]
C94  Value  [C0603]
C263  Value  [C0603]
C264  Value  [C0402]
C265  Value  [C0805]
C266  Value  [C0805]
C267  Value  [C0603]
C268  Value  [C0603]
C269  Value  [C0603]
C270  Value  [C0603]
C271  Value  [C0603]
C272  Value  [C0603]
C273  Value  [C0603]
C275  Value  [C0603]
C276  Value  [C0603]
C278  Value  [C0603]
C279  Value  [C0603]
D1  Value  [LED0805]
D2  Value  [C0402]
D3  Value  [LED0805]
L1  Value  [L4018]
L2  Value  [L4018]
L3  Value  [L4018]
L5  Value  [L4018]
L6  Value  [L4018]
L7  Value  [L4018]
L11  Value  [CD32]
OD1  Value  [SOD123]
OL1  Value  [CD43]
OU1  Value  [SOT23-6]
Q4  Value  [DFN8P0_65B2_00X2_00H0_75]
R11  Value  [R0402]
R12  Value  [R0402]
R14  Value  [R0402]
R17  Value  [R0402]
R18  Value  [R0402]
R19  Value  [R0402]
R22  Value  [R0402]
R23  Value  [R0402]
R319  Value  [R0805]
R328  Value  [R0402]
R329  Value  [R0402]
R463  Value  [R0805]
SW9  Value  [SW4]
TP61  Value  [TP_SMD]
TP62  Value  [TP_SMD]
TP70  Value  [TP_SMD]
TP71  Value  [TP_SMD]
U28  Value  [BGA218_P0_65B11X11]  (parts A,C,D of 4)

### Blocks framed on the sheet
DCIN: R463
OPTION: D1 R11
A: R328
B: R329

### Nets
ALDO1: C74.2 R328.2 U28.R6(value)  [also labelled VCC18-CSI2, VCC18-DSI, VCC18-EFUSE, VCC18-HDMI]
ALDO2: C76.2 U28.T4(value)  [also labelled CPVDD, LDOIN, VCC18-ADC, VCC18-PLL, VDD-DRAMPLL, VDD18-LPDDR]
ALDO3: C78.2 U28.T5(value)  [also labelled AVCC, VCC-PL]
AVDD-CSI: C275.1 U28.E10(value)  [also labelled DLDO4]
BB-VBAT: C264.1 C268.2 C269.2 L11.2 Q4.1(D1) Q4.2(D2) Q4.5(D3) Q4.6(D4) Q4.8(D5) R319.2 U28.L16(value)  [also labelled VBAT-EXT]
DC1-SW: C273.1 U28.J5(value)  [also labelled VCC-LCD]
DCDC1: C53.2 C82.1 C272.1 L1.2 OU1.4(value) R18.2 R329.2 U28.F16(value) U28.J6(value) U28.K6(value)  [also labelled VCC-CARD, VCC-IO, VCC-IO1, VCC-NAND, VCC-USB0]
DCDC6: C69.2 L7.2 U28.E12(value)  [also labelled VDD-SYS, VDD09-HDMI, VDD09-USB0]
DCIN: C265.2 R463.1 U28.N15(value) U28.N16(value)
DLDO1: C279.1 U28.F7(value)  [also labelled VCC-IO2, VCC-WIFI-IO]
DLDO2: C75.1 U28.F8(value)  [also labelled VCC-MIPI]
DLDO3: C77.1 U28.F10(value)
DVDD-CSI-F: C271.1 U28.E16(value)  [also labelled ELDO3]
ELDO1: C83.1 U28.G15(value)
ELDO2: C278.1 U28.D16(value)  [also labelled VCC-DSI]
FLDO1: C89.2 U28.E15(value)  [also labelled VCC12-HSIC]
FLDO2: C90.2 U28.F14(value)  [also labelled VDD-CPUS]
GND: C50.2 C53.1 C56.2 C57.2 C59.2 C61.2 C63.2 C64.2 C65.1 C66.2 C67.2 C68.2 C69.1 C70.1 C71.1 C72.2 C74.1 C75.2 C76.1 C77.2 C78.1 C79.1 C81.1 C82.2 C83.2 C88.1 C89.1 C90.1 C91.1 C92.1 C93.1 C94.1 C263.1 C265.1 C266.1 C267.1 C268.1 C269.1 C270.1 C271.2 C272.2 C273.2 C275.2 C276.1 C278.2 C279.2 D2.2(CATHODE) D3.2(CATHODE) OU1.2(value) R14.2 R19.2 R23.2 SW9.2 SW9.3 SW9.4 TP62.1(TP) TP71.1(TP) U28.D4(value) U28.D5(value) U28.D6(value) U28.D7(value) U28.E4(value) U28.E5(value) U28.E7(value) U28.F3(value) U28.F4(value) U28.F5(value) U28.F6(value) U28.G3(value) U28.G4(value) U28.G5(value) U28.G6(value) U28.G7(value) U28.G8(value) U28.G9(value) U28.G10(value) U28.G11(value) U28.G12(value) U28.G13(value) U28.G14(value) U28.H3(value) U28.H4(value) U28.H5(value) U28.H6(value) U28.H7(value) U28.H8(value) U28.H9(value) U28.H10(value) U28.H11(value) U28.H12(value) U28.H13(value) U28.H14(value) U28.J7(value) U28.J8(value) U28.J9(value) U28.J10(value) U28.J11(value) U28.J12(value) U28.J13(value) U28.J14(value) U28.K7(value) U28.K8(value) U28.K9(value) U28.K10(value) U28.K11(value) U28.K12(value) U28.K13(value) U28.K14(value) U28.L7(value) U28.L8(value) U28.L9(value) U28.L10(value) U28.L11(value) U28.L12(value) U28.L13(value) U28.L14(value) U28.M7(value) U28.M8(value) U28.M9(value) U28.M10(value) U28.M11(value) U28.M12(value) U28.M13(value) U28.M14(value) U28.N7(value) U28.N8(value) U28.N9(value) U28.N10(value) U28.N11(value) U28.N12(value) U28.N13(value) U28.N14(value) U28.P4(value) U28.P5(value) U28.P7(value) U28.P8(value) U28.P9(value) U28.P10(value) U28.P11(value) U28.P12(value) U28.P13(value) U28.P14(value)
GPIO0-LDO: C276.2 U28.T8(value)  [also labelled VCC-CTP]
GPIO1-LDO: C81.2 U28.T7(value)
PS: C50.1 C57.1 C61.1 C64.1 C66.1 C68.1 C71.2 C72.1 C91.2 C92.2 C263.2 C270.2 OL1.1 OU1.5(value) Q4.4(S1) Q4.7(S2) R11.1 U28.E9(value) U28.F11(value) U28.F13(value) U28.H16(value) U28.J15(value) U28.J16(value) U28.L6(value) U28.M5(value) U28.M6(value) U28.P15(value) U28.P16(value) U28.R7(value) U28.R10(value) U28.T9(value) U28.T10(value)
USB-5V: C93.2 C94.2 OD1.2 R22.1  [also labelled VCC-5V]
USBVBUS: C266.2 R463.2 U28.R16(value)
VBAT: C264.2 C267.2 R319.1 TP70.1(TP) U28.L15(value)
VCC-DRAM: C65.2 C88.2 L6.2 U28.F12(value) U28.F15(value)
VCC-PD: R328.1 R329.1
VCC-RTC: C70.2 U28.T14(value)  [also labelled VCC18-LVDS, VDD-1V8]
VDD-CPUA: C56.1 L2.2
VDD-CPUB: C59.1 L3.2
VDD-GPU: C63.1 L5.2 U28.N4(value)
AP-RESET#: C79.2 R17.2 ; off-sheet AP-RESET#
PWRON: R12.2 TP61.1(TP) ; off-sheet PWRON
USB-DRVVBUS: U28.T16(value) ; off-sheet USB-DRVVBUS
VDDFB-CPUA: U28.T11(value) ; off-sheet VDDFB-CPUA
VDDFB-CPUB: U28.R11(value) ; off-sheet VDDFB-CPUB
NetC67_1: C67.1 R12.1 U28.M15(value)
NetD1_1: D1.1(ANODE) R11.2
NetD1_2: D1.2(CATHODE) U28.R15(value)
NetD2_1: D2.1(ANODE) R17.1 SW9.1
NetD3_1: D3.1(ANODE) R18.1
NetL1_1: L1.1 U28.L5(value)
NetL2_1: L2.1 U28.R12(value) U28.T12(value)
NetL3_1: L3.1 U28.R8(value) U28.R9(value)
NetL5_1: L5.1 U28.N6(value) U28.P6(value)
NetL6_1: L6.1 U28.C14(value) U28.D14(value)
NetL7_1: L7.1 U28.C12(value) U28.D12(value)
NetL11_1: L11.1 U28.K15(value) U28.K16(value)
NetOD1_1: OD1.1 OL1.2 OU1.1(value)
NetOU1_3: OU1.3(value) R22.2 R23.1
NetQ4_3: Q4.3(G) U28.T15(value)
NetR14_1: R14.1 U28.M16(value)
NetR19_1: R19.1 U28.R5(value)

Not connected (* = marked no-connect by the designer): OU1 6(value); U28 D15(value) G16(value) H15(value) R4(value) R13(value) R14(value) T3(value) T6(value) T13(value)

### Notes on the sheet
- PMIC
- IF use the battery temperature sensor: A=NC
  otherwise: A=10k
- BAT
- PS-5V
- connect the USBVBUS to DCIN
  if use usb power only
- Vth < 1.5V
  R < 30m ohm
  VGS < 4.5V
- (near C267) close to
  PMIC
- Battery
- 0.9V
- CAMERA
- If front & rear cameras have different power up
  timing sequence, please refer to the hardware
  design guide.
- 1.2V
- BB
- 1.2V - 1.5V
- MIPI LCD
- 1.8V
- 3.0V
- 5V
- OPTION
- (near D2) OPTION
- (near R328) If PD port use 1.8V
  mount A and NC B
- 3.1V
- (near R329) If PD port use 3.1V
  mount B and NC A
- For 3g

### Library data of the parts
C50 C53 C56 C57 C59 C61 C63-C66 C68-C72 C74-C78 C81-C83 C88-C94 C263-C273 C275 C276 C278 C279 = CAPACITOR_0_Dup1: PAGE: 1
C67 C79 = CAPACITOR_0_Dup3
D1 D3 = LED_0: PAGE: 1
D2 = 1_1.5KE100A: as D26 on sheet 12 CODEC
L1-L3 L5-L7 L11 OL1 = INDUCTOR_0
OD1 = DIODE_SCHOTTKY
OU1 = RT9266PE_0
Q4 = WPM4005_11
R11 = R
R12 R17 R19 R328 R329 = R_Dup1
R14 R18 R22 R23 R319 R463 = R_Dup2
SW9 = SW_PUSH: as SW8 on sheet 11 CARD-SENSOR-VIBRATOR
TP61 TP62 TP70 TP71 = T_POINT_R
U28 = AW1660_70_BGA218_1

## Sheet 06 CPU.SchDoc
size 420 x 297 mm
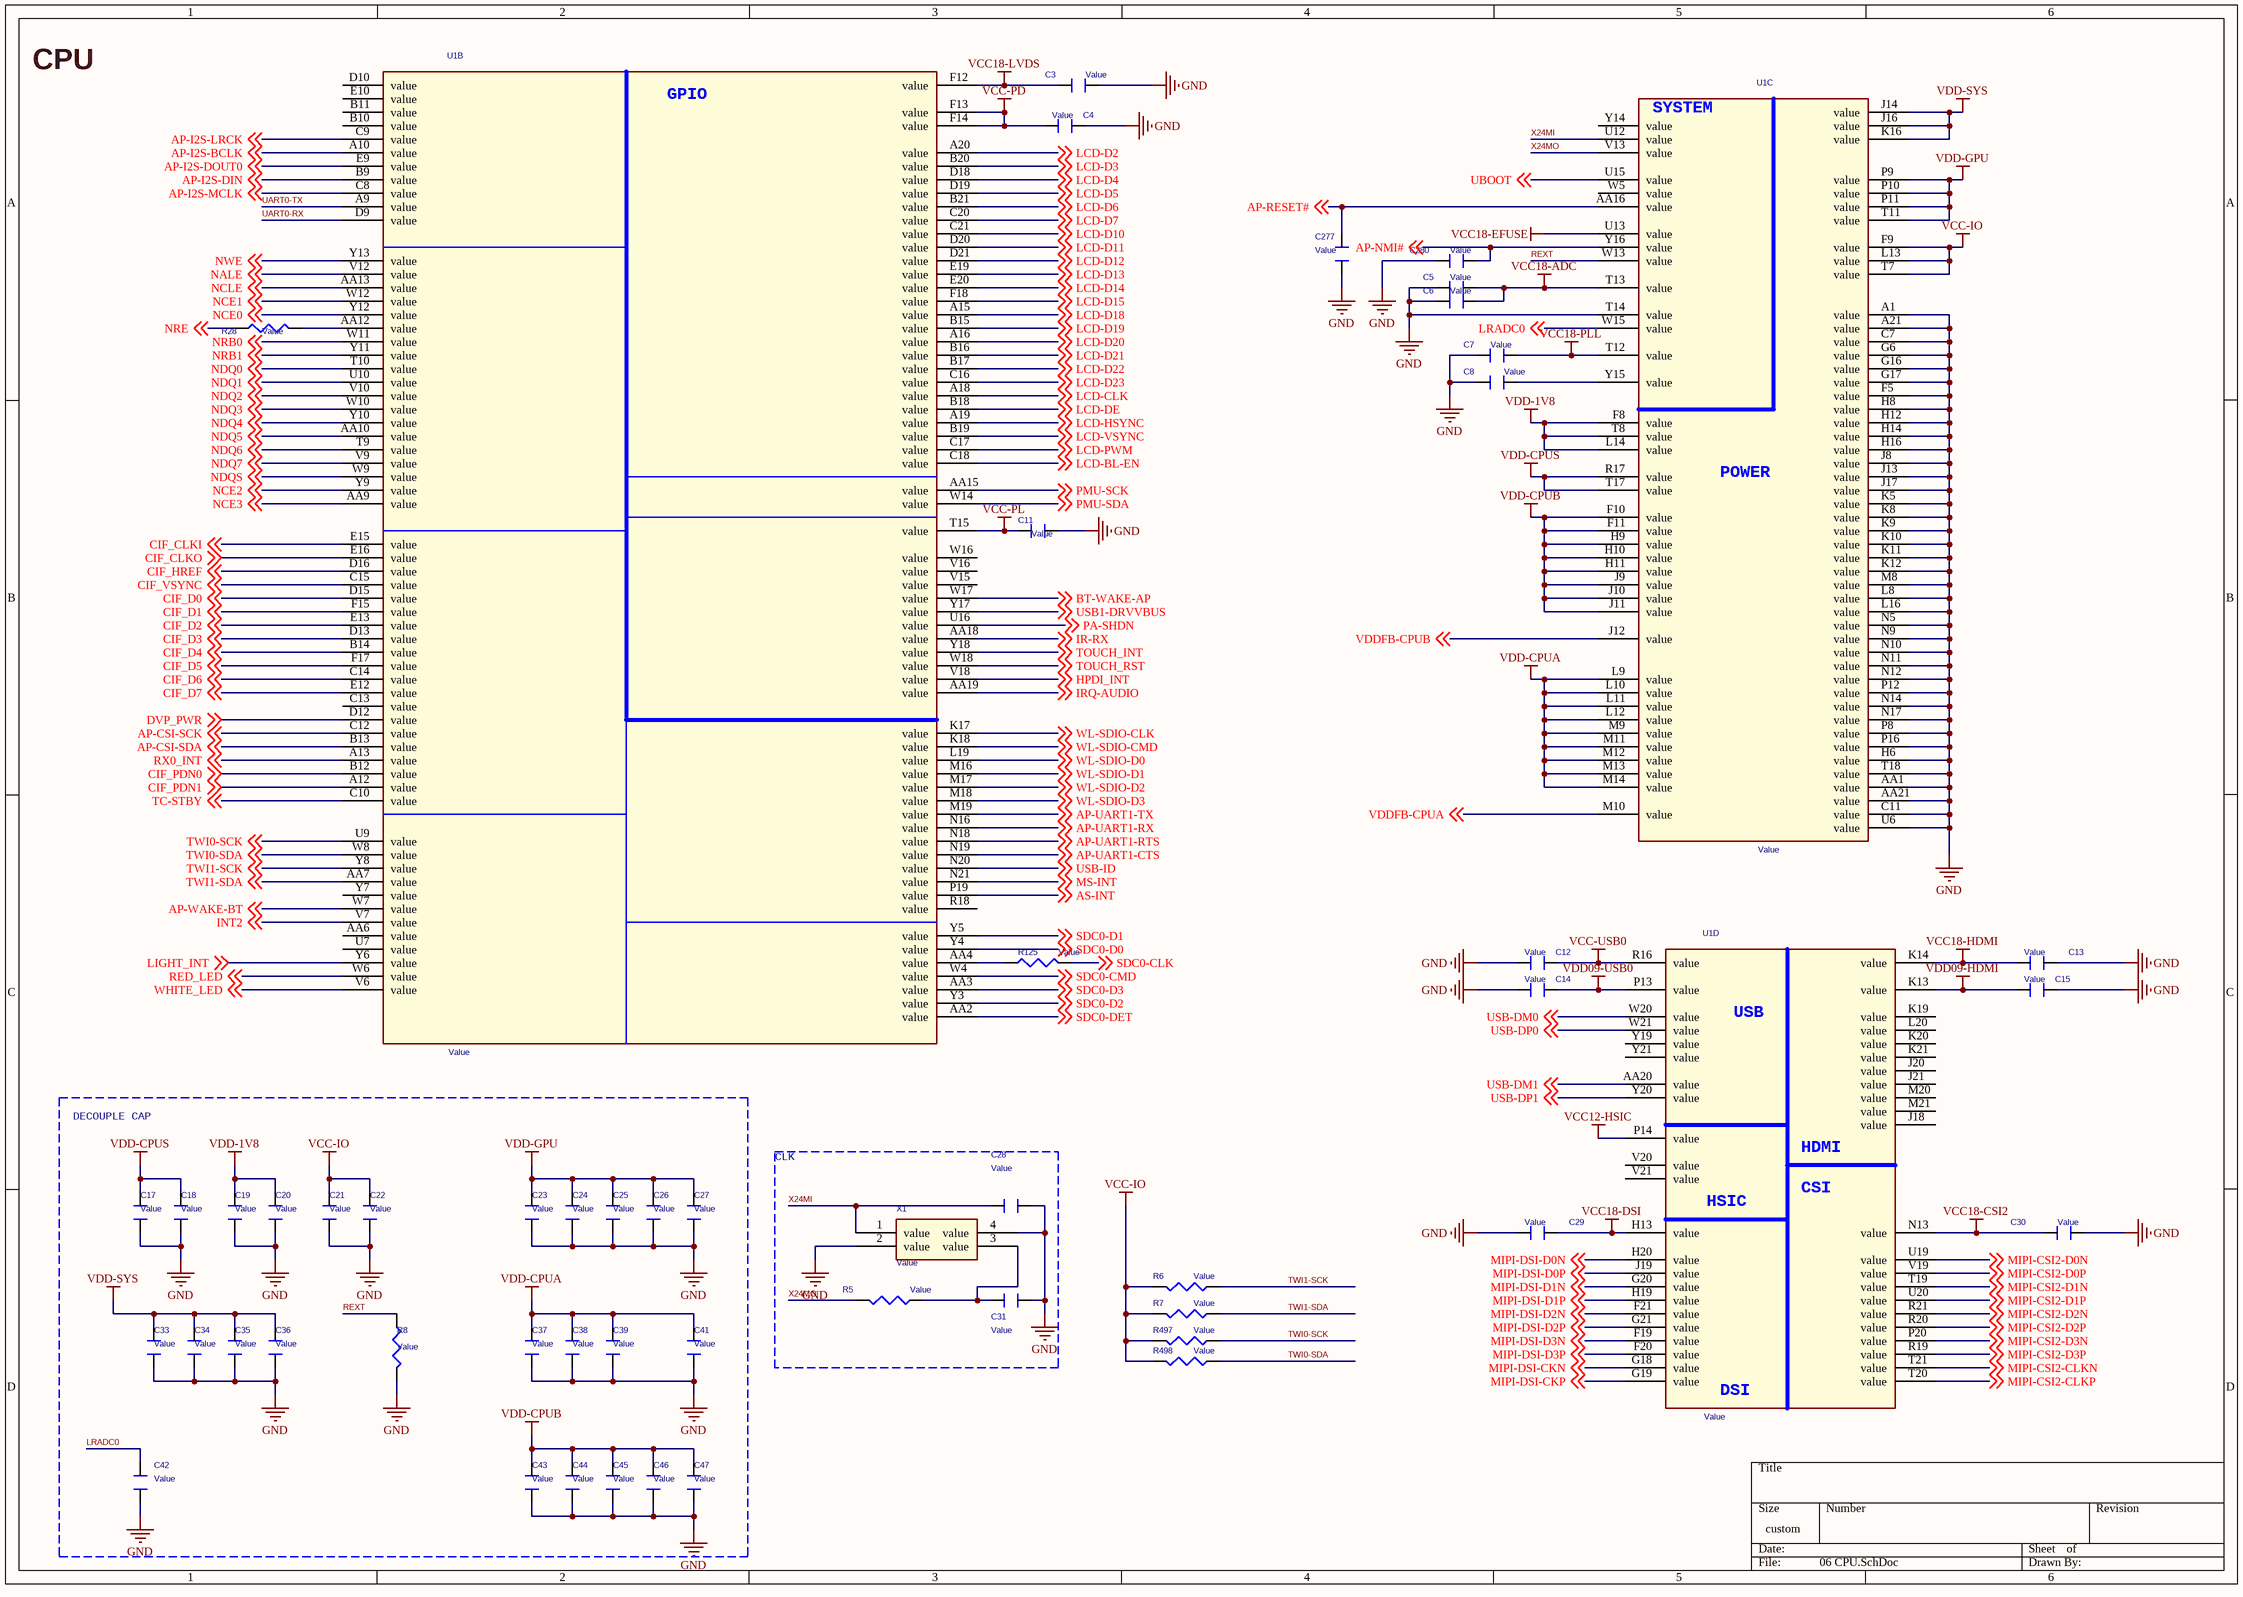
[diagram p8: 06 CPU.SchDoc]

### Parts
C3  Value  [C0402]
C4  Value  [C0402]
C5  Value  [C0402]
C6  Value  [C0603]
C7  Value  [C0402]
C8  Value  [C0402]
C11  Value  [C0402]
C12  Value  [C0402]
C13  Value  [C0402]
C14  Value  [C0402]
C15  Value  [C0402]
C17  Value  [C0402]
C18  Value  [C0402]
C19  Value  [C0402]
C20  Value  [C0402]
C21  Value  [C0402]
C22  Value  [C0402]
C23  Value  [C0603]
C24  Value  [C0402]
C25  Value  [C0402]
C26  Value  [C0402]
C27  Value  [C0402]
C28  Value  [C0402]
C29  Value  [C0402]
C30  Value  [C0402]
C31  Value  [C0402]
C33  Value  [C0402]
C34  Value  [C0402]
C35  Value  [C0402]
C36  Value  [C0402]
C37  Value  [C0603]
C38  Value  [C0402]
C39  Value  [C0402]
C41  Value  [C0402]
C42  Value  [C0402]
C43  Value  [C0603]
C44  Value  [C0402]
C45  Value  [C0402]
C46  Value  [C0402]
C47  Value  [C0402]
C277  Value  [C0402]
C280  Value  [C0402]
R5  Value  [R0402]
R6  Value  [R0402]
R7  Value  [R0402]
R8  Value  [R0402]
R28  Value  [R0402]
R125  Value  [R0402]
R497  Value  [R0402]
R498  Value  [R0402]
U1  Value  [BGA345P0_65B14X14]  (parts B,C,D of 4)
X1  Value  [CRY-3225]

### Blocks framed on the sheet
DECOUPLE CAP: C17-C27 C33-C39 C41-C47 R8
CLK: C28 C31 R5 X1

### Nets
GND: C3.2 C4.2 C5.1 C6.1 C7.2 C8.2 C11.1 C12.1 C13.2 C14.1 C15.2 C17.1 C18.1 C19.1 C20.1 C21.1 C22.1 C23.1 C24.1 C25.1 C26.1 C27.1 C28.1 C29.1 C30.1 C31.1 C33.1 C34.1 C35.1 C36.1 C37.1 C38.1 C39.1 C41.1 C42.1 C43.1 C44.1 C45.1 C46.1 C47.1 C277.2 C280.1 R8.2 U1.A1(value) U1.A21(value) U1.AA1(value) U1.AA21(value) U1.C7(value) U1.C11(value) U1.F5(value) U1.G6(value) U1.G16(value) U1.G17(value) U1.H6(value) U1.H8(value) U1.H12(value) U1.H14(value) U1.H16(value) U1.J8(value) U1.J13(value) U1.J17(value) U1.K5(value) U1.K8(value) U1.K9(value) U1.K10(value) U1.K11(value) U1.K12(value) U1.L8(value) U1.L16(value) U1.M8(value) U1.N5(value) U1.N9(value) U1.N10(value) U1.N11(value) U1.N12(value) U1.N14(value) U1.N17(value) U1.P8(value) U1.P12(value) U1.P16(value) U1.T14(value) U1.T18(value) U1.U6(value) X1.2(value) X1.4(value)
VCC12-HSIC: U1.P14(value)  [project net FLDO1]
VCC18-ADC: C5.2 C6.2 C7.1 U1.T12(value) U1.T13(value)  [also labelled VCC18-PLL]  [project net ALDO2]
VCC18-CSI2: C13.1 C29.2 C30.2 U1.H13(value) U1.K14(value) U1.N13(value) U1.U13(value)  [also labelled VCC18-DSI, VCC18-EFUSE, VCC18-HDMI]  [project net ALDO1]
VCC18-LVDS: C3.1 C19.2 C20.2 U1.F8(value) U1.F12(value) U1.L14(value) U1.T8(value)  [also labelled VDD-1V8]  [project net VCC-RTC]
VCC-IO: C12.2 C21.2 C22.2 R6.2 R7.2 R497.2 R498.2 U1.F9(value) U1.L13(value) U1.R16(value) U1.T7(value)  [also labelled VCC-USB0]  [project net DCDC1]
VCC-PD: C4.1 U1.F13(value) U1.F14(value)
VCC-PL: C11.2 U1.T15(value)  [project net ALDO3]
VDD-CPUA: C37.2 C38.2 C39.2 C41.2 U1.L9(value) U1.L10(value) U1.L11(value) U1.L12(value) U1.M9(value) U1.M11(value) U1.M12(value) U1.M13(value) U1.M14(value)
VDD-CPUB: C43.2 C44.2 C45.2 C46.2 C47.2 U1.F10(value) U1.F11(value) U1.H9(value) U1.H10(value) U1.H11(value) U1.J9(value) U1.J10(value) U1.J11(value)
VDD-CPUS: C17.2 C18.2 U1.R17(value) U1.T17(value)  [project net FLDO2]
VDD-GPU: C23.2 C24.2 C25.2 C26.2 C27.2 U1.P9(value) U1.P10(value) U1.P11(value) U1.T11(value)
VDD-SYS: C14.2 C15.1 C33.2 C34.2 C35.2 C36.2 U1.J14(value) U1.J16(value) U1.K13(value) U1.K16(value) U1.P13(value)  [also labelled VDD09-HDMI, VDD09-USB0]  [project net DCDC6]
AP-CSI-SCK: U1.C12(value) ; off-sheet AP-CSI-SCK  [project net I2C3_SCL_CAM]
AP-CSI-SDA: U1.B13(value) ; off-sheet AP-CSI-SDA  [project net I2C3_SDA_CAM]
AP-I2S-BCLK: U1.A10(value) ; off-sheet AP-I2S-BCLK
AP-I2S-DIN: U1.B9(value) ; off-sheet AP-I2S-DIN
AP-I2S-DOUT0: U1.E9(value) ; off-sheet AP-I2S-DOUT0
AP-I2S-LRCK: U1.C9(value) ; off-sheet AP-I2S-LRCK
AP-I2S-MCLK: U1.C8(value) ; off-sheet AP-I2S-MCLK
AP-NMI#: C280.2 U1.Y16(value) ; off-sheet AP-NMI#
AP-RESET#: C277.1 U1.AA16(value) ; off-sheet AP-RESET#
AP-UART1-CTS: U1.N19(value) ; off-sheet AP-UART1-CTS  [project net BT-UART-RTS]
AP-UART1-RTS: U1.N18(value) ; off-sheet AP-UART1-RTS  [project net BT-UART-CTS]
AP-UART1-RX: U1.N16(value) ; off-sheet AP-UART1-RX  [project net BT-UART-TX]
AP-UART1-TX: U1.M19(value) ; off-sheet AP-UART1-TX  [project net BT-UART-RX]
AP-WAKE-BT: U1.W7(value) ; off-sheet AP-WAKE-BT
AS-INT: U1.P19(value) ; off-sheet AS-INT  [project net GSEN_INT]
BT-WAKE-AP: U1.W17(value) ; off-sheet BT-WAKE-AP
CIF_CLKI: U1.E15(value) ; off-sheet CIF_CLKI
CIF_CLKO: U1.E16(value) ; off-sheet CIF_CLKO
CIF_D0: U1.D15(value) ; off-sheet CIF_D0
CIF_D1: U1.F15(value) ; off-sheet CIF_D1
CIF_D2: U1.E13(value) ; off-sheet CIF_D2
CIF_D3: U1.D13(value) ; off-sheet CIF_D3
CIF_D4: U1.B14(value) ; off-sheet CIF_D4
CIF_D5: U1.F17(value) ; off-sheet CIF_D5
CIF_D6: U1.C14(value) ; off-sheet CIF_D6
CIF_D7: U1.E12(value) ; off-sheet CIF_D7
CIF_HREF: U1.D16(value) ; off-sheet CIF_HREF
CIF_PDN0: U1.B12(value) ; off-sheet CIF_PDN0
CIF_PDN1: U1.A12(value) ; off-sheet CIF_PDN1
CIF_VSYNC: U1.C15(value) ; off-sheet CIF_VSYNC
DVP_PWR: U1.D12(value) ; off-sheet DVP_PWR
HPDI_INT: U1.V18(value) ; off-sheet HPDI_INT
INT2: U1.V7(value) ; off-sheet INT2
IR-RX: U1.AA18(value) ; off-sheet IR-RX
IRQ-AUDIO: U1.AA19(value) ; off-sheet IRQ-AUDIO
LCD-BL-EN: U1.C18(value) ; off-sheet LCD-BL-EN
LCD-CLK: U1.A18(value) ; off-sheet LCD-CLK
LCD-D2: U1.A20(value) ; off-sheet LCD-D2
LCD-D3: U1.B20(value) ; off-sheet LCD-D3
LCD-D4: U1.D18(value) ; off-sheet LCD-D4
LCD-D5: U1.D19(value) ; off-sheet LCD-D5
LCD-D6: U1.B21(value) ; off-sheet LCD-D6
LCD-D7: U1.C20(value) ; off-sheet LCD-D7
LCD-D10: U1.C21(value) ; off-sheet LCD-D10
LCD-D11: U1.D20(value) ; off-sheet LCD-D11
LCD-D12: U1.D21(value) ; off-sheet LCD-D12
LCD-D13: U1.E19(value) ; off-sheet LCD-D13
LCD-D14: U1.E20(value) ; off-sheet LCD-D14
LCD-D15: U1.F18(value) ; off-sheet LCD-D15
LCD-D18: U1.A15(value) ; off-sheet LCD-D18
LCD-D19: U1.B15(value) ; off-sheet LCD-D19
LCD-D20: U1.A16(value) ; off-sheet LCD-D20
LCD-D21: U1.B16(value) ; off-sheet LCD-D21
LCD-D22: U1.B17(value) ; off-sheet LCD-D22
LCD-D23: U1.C16(value) ; off-sheet LCD-D23
LCD-DE: U1.B18(value) ; off-sheet LCD-DE
LCD-HSYNC: U1.A19(value) ; off-sheet LCD-HSYNC
LCD-PWM: U1.C17(value) ; off-sheet LCD-PWM
LCD-VSYNC: U1.B19(value) ; off-sheet LCD-VSYNC
LIGHT_INT: U1.Y6(value) ; off-sheet LIGHT_INT
LRADC0: C42.2 U1.W15(value) ; off-sheet LRADC0
MIPI-CSI2-CLKN: U1.T21(value) ; off-sheet MIPI-CSI2-CLKN
MIPI-CSI2-CLKP: U1.T20(value) ; off-sheet MIPI-CSI2-CLKP
MIPI-CSI2-D0N: U1.U19(value) ; off-sheet MIPI-CSI2-D0N
MIPI-CSI2-D0P: U1.V19(value) ; off-sheet MIPI-CSI2-D0P
MIPI-CSI2-D1N: U1.T19(value) ; off-sheet MIPI-CSI2-D1N
MIPI-CSI2-D1P: U1.U20(value) ; off-sheet MIPI-CSI2-D1P
MIPI-CSI2-D2N: U1.R21(value) ; off-sheet MIPI-CSI2-D2N
MIPI-CSI2-D2P: U1.R20(value) ; off-sheet MIPI-CSI2-D2P
MIPI-CSI2-D3N: U1.P20(value) ; off-sheet MIPI-CSI2-D3N
MIPI-CSI2-D3P: U1.R19(value) ; off-sheet MIPI-CSI2-D3P
MIPI-DSI-CKN: U1.G18(value) ; off-sheet MIPI-DSI-CKN  [project net DSI-CKN]
MIPI-DSI-CKP: U1.G19(value) ; off-sheet MIPI-DSI-CKP  [project net DSI-CKP]
MIPI-DSI-D0N: U1.H20(value) ; off-sheet MIPI-DSI-D0N  [project net DSI-D0N]
MIPI-DSI-D0P: U1.J19(value) ; off-sheet MIPI-DSI-D0P  [project net DSI-D0P]
MIPI-DSI-D1N: U1.G20(value) ; off-sheet MIPI-DSI-D1N  [project net DSI-D1N]
MIPI-DSI-D1P: U1.H19(value) ; off-sheet MIPI-DSI-D1P  [project net DSI-D1P]
MIPI-DSI-D2N: U1.F21(value) ; off-sheet MIPI-DSI-D2N  [project net DSI-D2N]
MIPI-DSI-D2P: U1.G21(value) ; off-sheet MIPI-DSI-D2P  [project net DSI-D2P]
MIPI-DSI-D3N: U1.F19(value) ; off-sheet MIPI-DSI-D3N  [project net DSI-D3N]
MIPI-DSI-D3P: U1.F20(value) ; off-sheet MIPI-DSI-D3P  [project net DSI-D3P]
MS-INT: U1.N21(value) ; off-sheet MS-INT
NALE: U1.V12(value) ; off-sheet NALE
NCE0: U1.Y12(value) ; off-sheet NCE0
NCE1: U1.W12(value) ; off-sheet NCE1
NCE2: U1.Y9(value) ; off-sheet NCE2
NCE3: U1.AA9(value) ; off-sheet NCE3
NCLE: U1.AA13(value) ; off-sheet NCLE
NDQ0: U1.T10(value) ; off-sheet NDQ0  [project net eMMC-D0]
NDQ1: U1.U10(value) ; off-sheet NDQ1  [project net eMMC-D1]
NDQ2: U1.V10(value) ; off-sheet NDQ2  [project net eMMC-D2]
NDQ3: U1.W10(value) ; off-sheet NDQ3  [project net eMMC-D3]
NDQ4: U1.Y10(value) ; off-sheet NDQ4  [project net eMMC-D4]
NDQ5: U1.AA10(value) ; off-sheet NDQ5  [project net eMMC-D5]
NDQ6: U1.T9(value) ; off-sheet NDQ6  [project net eMMC-D6]
NDQ7: U1.V9(value) ; off-sheet NDQ7  [project net eMMC-D7]
NDQS: U1.W9(value) ; off-sheet NDQS  [project net eMMC-RST]
NRB0: U1.W11(value) ; off-sheet NRB0  [project net eMMC-CMD]
NRB1: U1.Y11(value) ; off-sheet NRB1
NRE: R28.1 ; off-sheet NRE  [project net eMMC-CLK]
NWE: U1.Y13(value) ; off-sheet NWE
PA-SHDN: U1.U16(value) ; off-sheet PA-SHDN
PMU-SCK: U1.AA15(value) ; off-sheet PMU-SCK  [project net CODEC-SCK]
PMU-SDA: U1.W14(value) ; off-sheet PMU-SDA  [project net CODEC-SDA]
RED_LED: U1.W6(value) ; off-sheet RED_LED
REXT: R8.1 U1.W13(value)
RX0_INT: U1.A13(value) ; off-sheet RX0_INT
SDC0-CLK: R125.2 ; off-sheet SDC0-CLK
SDC0-CMD: U1.W4(value) ; off-sheet SDC0-CMD
SDC0-D0: U1.Y4(value) ; off-sheet SDC0-D0
SDC0-D1: U1.Y5(value) ; off-sheet SDC0-D1
SDC0-D2: U1.Y3(value) ; off-sheet SDC0-D2
SDC0-D3: U1.AA3(value) ; off-sheet SDC0-D3
SDC0-DET: U1.AA2(value) ; off-sheet SDC0-DET
TC-STBY: U1.C10(value) ; off-sheet TC-STBY
TOUCH_INT: U1.Y18(value) ; off-sheet TOUCH_INT
TOUCH_RST: U1.W18(value) ; off-sheet TOUCH_RST
TWI0-SCK: R497.1 U1.U9(value) ; off-sheet TWI0-SCK  [project net SENSOR0-TWI-SCK]
TWI0-SDA: R498.1 U1.W8(value) ; off-sheet TWI0-SDA  [project net SENSOR0-TWI-SDA]
TWI1-SCK: R6.1 U1.Y8(value) ; off-sheet TWI1-SCK  [project net SENSOR-TWI-SCK]
TWI1-SDA: R7.1 U1.AA7(value) ; off-sheet TWI1-SDA  [project net SENSOR-TWI-SDA]
UART0-RX: U1.D9(value)
UART0-TX: U1.A9(value)
UBOOT: U1.U15(value) ; off-sheet UBOOT
USB1-DRVVBUS: U1.Y17(value) ; off-sheet USB1-DRVVBUS
USB-DM0: U1.W20(value) ; off-sheet USB-DM0
USB-DM1: U1.AA20(value) ; off-sheet USB-DM1
USB-DP0: U1.W21(value) ; off-sheet USB-DP0
USB-DP1: U1.Y20(value) ; off-sheet USB-DP1
USB-ID: U1.N20(value) ; off-sheet USB-ID
VDDFB-CPUA: U1.M10(value) ; off-sheet VDDFB-CPUA
VDDFB-CPUB: U1.J12(value) ; off-sheet VDDFB-CPUB
WHITE_LED: U1.V6(value) ; off-sheet WHITE_LED
WL-SDIO-CLK: U1.K17(value) ; off-sheet WL-SDIO-CLK
WL-SDIO-CMD: U1.K18(value) ; off-sheet WL-SDIO-CMD
WL-SDIO-D0: U1.L19(value) ; off-sheet WL-SDIO-D0
WL-SDIO-D1: U1.M16(value) ; off-sheet WL-SDIO-D1
WL-SDIO-D2: U1.M17(value) ; off-sheet WL-SDIO-D2
WL-SDIO-D3: U1.M18(value) ; off-sheet WL-SDIO-D3
X24MI: C28.2 U1.U12(value) X1.1(value)
X24MO: R5.2 U1.V13(value)
NetC8_1: C8.1 U1.Y15(value)
NetC31_2: C31.2 R5.1 X1.3(value)
NetR28_2: R28.2 U1.AA12(value)
NetR125_1: R125.1 U1.AA4(value)

Not connected (* = marked no-connect by the designer): U1 AA6(value) B10(value) B11(value) C13(value) D10(value) E10(value) J18(value) J20(value) J21(value) K19(value) K20(value) K21(value) L20(value) M20(value) M21(value) R18(value) U7(value) V15(value) V16(value) V20(value) V21(value) W5(value) W16(value) Y7(value) Y14(value) Y19(value) Y21(value)

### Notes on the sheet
- CPU

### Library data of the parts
C3 C4 = CAPACITOR_0_Dup3: PAGE: 2; mypage: 09
C5-C8 C12-C15 C17-C27 C29 C30 C33-C39 C41 C43-C47 = CAPACITOR_0_Dup3
C11 C28 C31 C42 C277 C280 = CAPACITOR_0_Dup3: PAGE: 2
R5 = R_Dup1
R6-R8 R125 R497 R498 = R_Dup2
R28 = R_Dup2: mypage: 08
U1 = A83_0
X1 = CRYSTAL-4_2: Crystal 24MHz 20pF 10ppm  -30 to +85; PART NUMBER: 7M24000004; Vendor: TXC; SPREADWIN PN: U3000019A

## Sheet 05 LPDDR3_32X1.SchDoc
size 420 x 297 mm
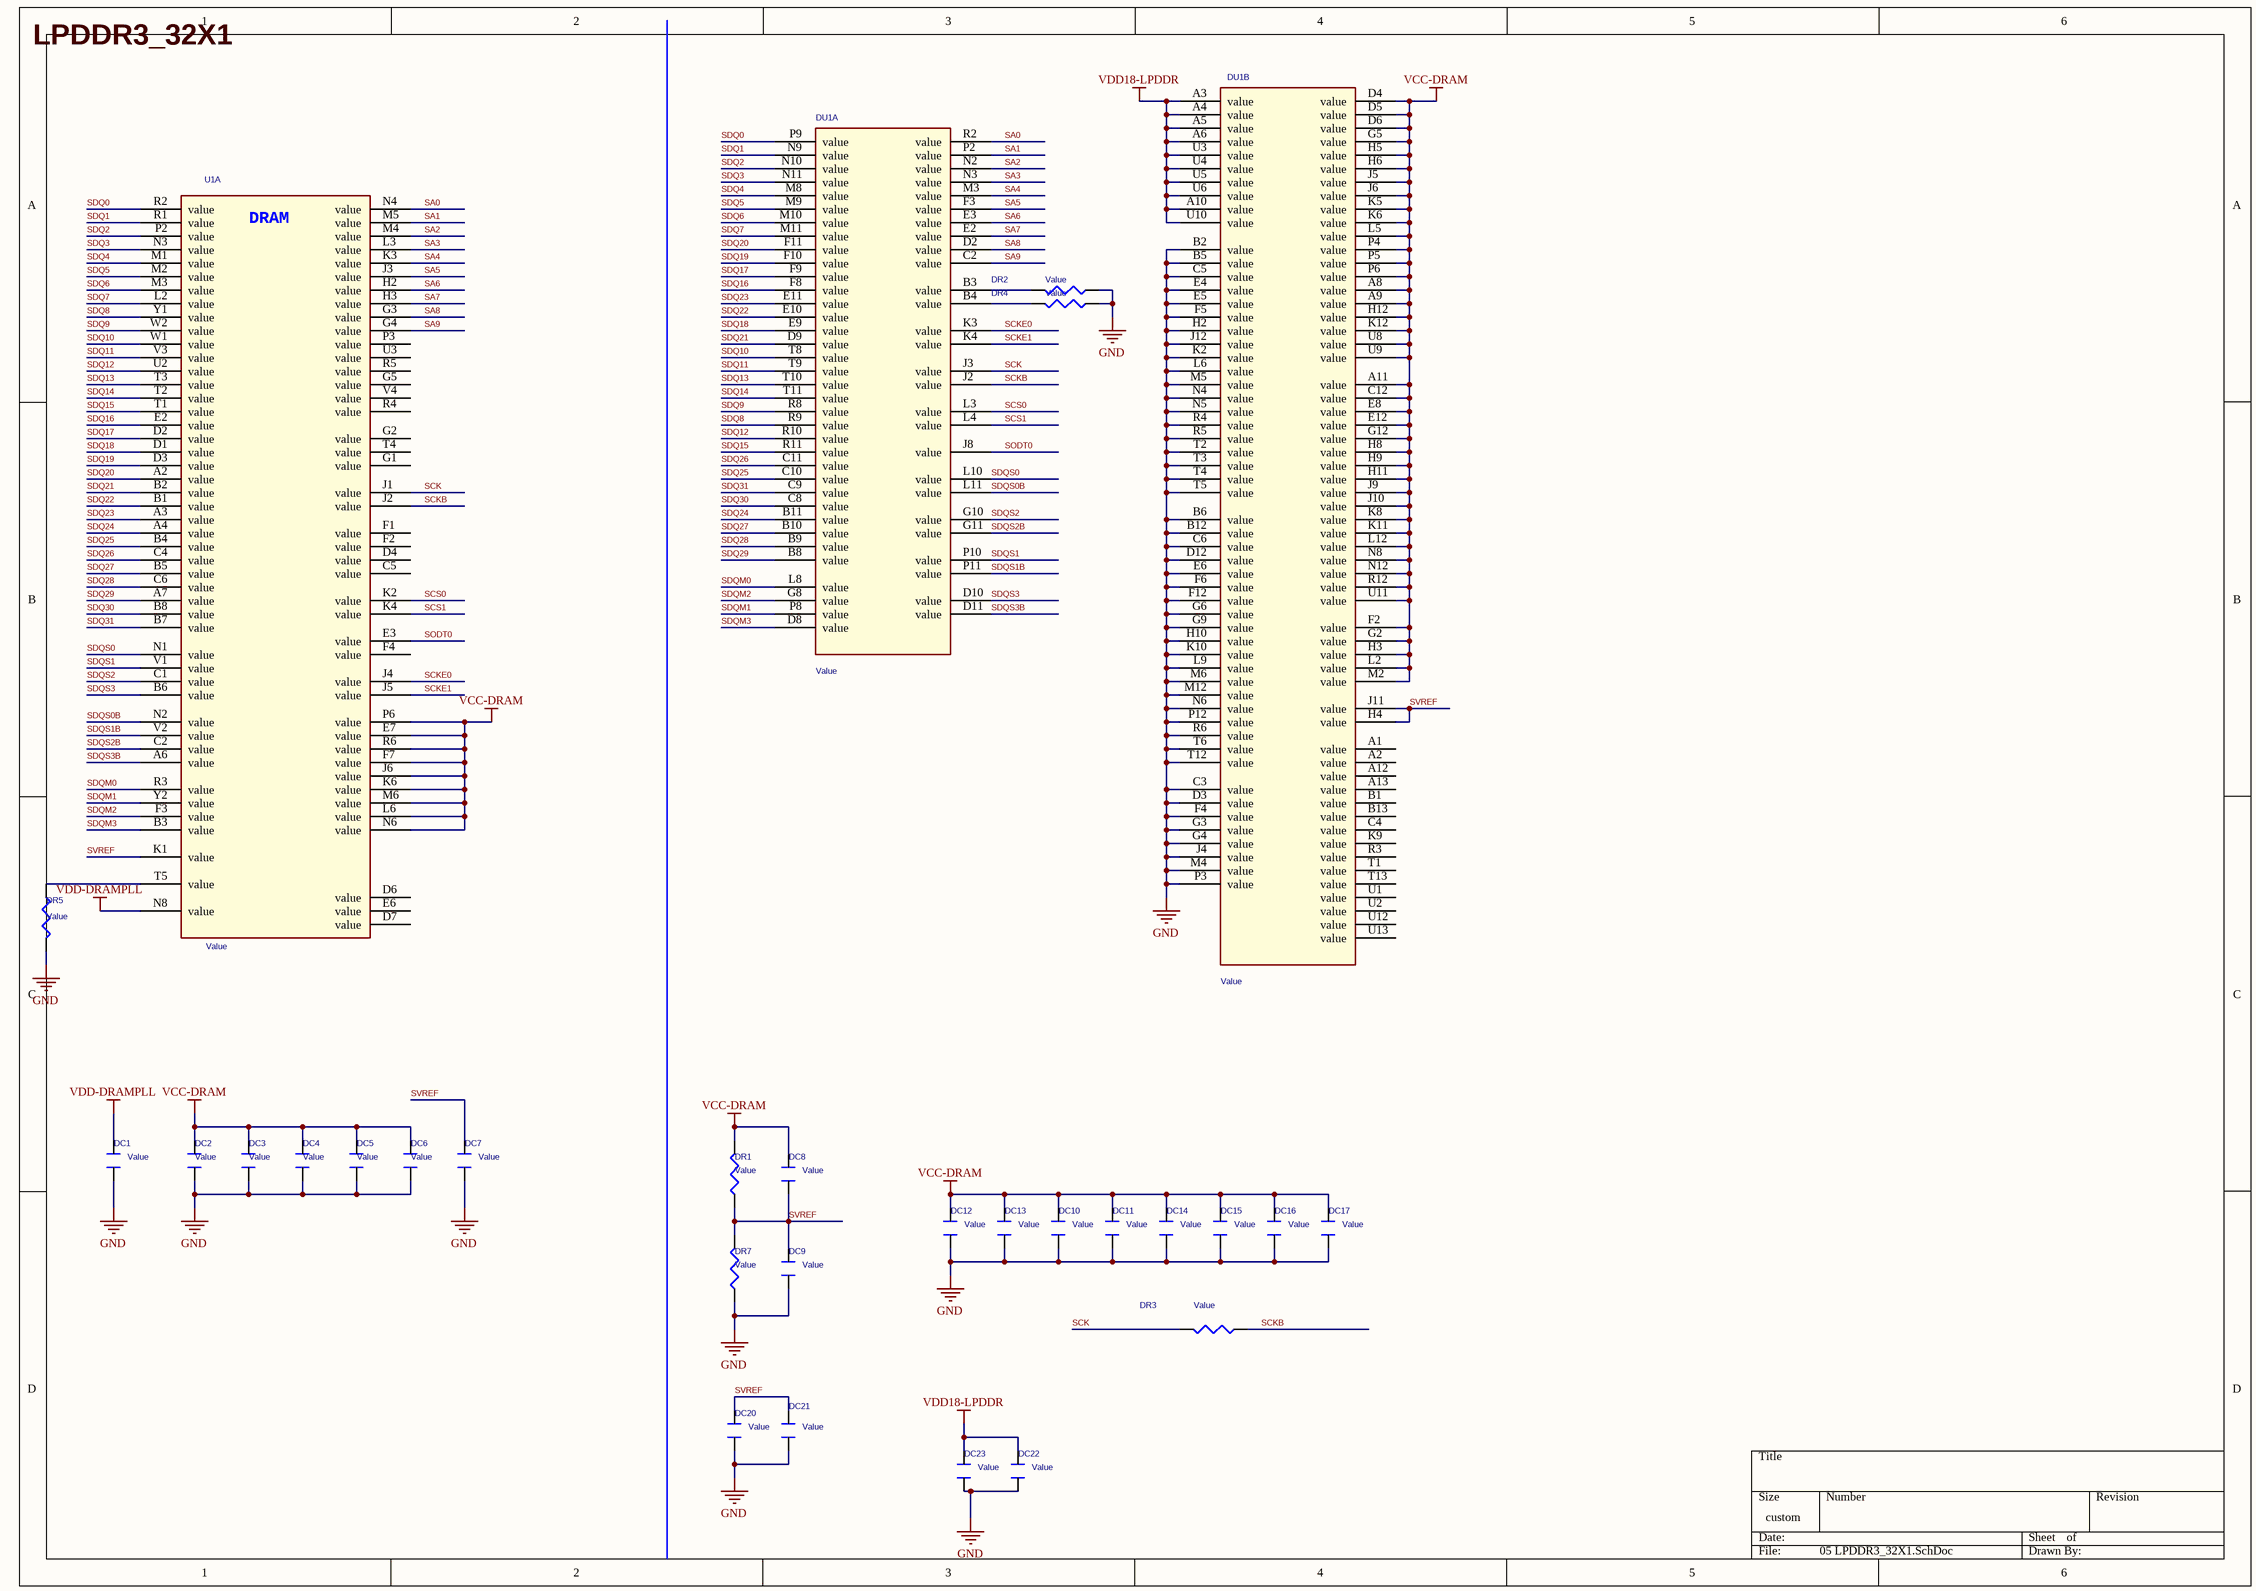
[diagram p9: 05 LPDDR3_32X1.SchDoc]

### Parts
DC1  Value  [C0402]
DC2  Value  [C0603]
DC3  Value  [C0402]
DC4  Value  [C0402]
DC5  Value  [C0402]
DC6  Value  [C0402]
DC7  Value  [C0402]
DC8  Value  [C0402]
DC9  Value  [C0402]
DC10  Value  [C0402]
DC11  Value  [C0402]
DC12  Value  [C0603]
DC13  Value  [C0402]
DC14  Value  [C0402]
DC15  Value  [C0402]
DC16  Value  [C0402]
DC17  Value  [C0402]
DC20  Value  [C0402]
DC21  Value  [C0402]
DC22  Value  [C0402]
DC23  Value  [C0402]
DR1  Value  [R0402]
DR2  Value  [0805]
DR3  Value  [R0402]
DR4  Value  [0805]
DR5  Value  [R0402]
DR7  Value  [R0402]
DU1  Value  [BGA178P0_8X0_65B13X11_5H1_13]  (parts A,B of 2)
U1  Value  [BGA345P0_65B14X14]  (part A of 4)

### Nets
GND: DC1.1 DC2.1 DC3.1 DC4.1 DC5.1 DC6.1 DC7.1 DC9.1 DC10.1 DC11.1 DC12.1 DC13.1 DC14.1 DC15.1 DC16.1 DC17.1 DC20.1 DC21.1 DC22.1 DC23.1 DR2.1 DR4.1 DR5.2 DR7.1 DU1.B2(value) DU1.B5(value) DU1.B6(value) DU1.B12(value) DU1.C3(value) DU1.C5(value) DU1.C6(value) DU1.D3(value) DU1.D12(value) DU1.E4(value) DU1.E5(value) DU1.E6(value) DU1.F4(value) DU1.F5(value) DU1.F6(value) DU1.F12(value) DU1.G3(value) DU1.G4(value) DU1.G6(value) DU1.G9(value) DU1.H2(value) DU1.H10(value) DU1.J4(value) DU1.J12(value) DU1.K2(value) DU1.K10(value) DU1.L6(value) DU1.L9(value) DU1.M4(value) DU1.M5(value) DU1.M6(value) DU1.M12(value) DU1.N4(value) DU1.N5(value) DU1.N6(value) DU1.P3(value) DU1.P12(value) DU1.R4(value) DU1.R5(value) DU1.R6(value) DU1.T2(value) DU1.T3(value) DU1.T4(value) DU1.T5(value) DU1.T6(value) DU1.T12(value)
VCC-DRAM: DC2.2 DC3.2 DC4.2 DC5.2 DC6.2 DC8.2 DC10.2 DC11.2 DC12.2 DC13.2 DC14.2 DC15.2 DC16.2 DC17.2 DR1.2 DU1.A8(value) DU1.A9(value) DU1.A11(value) DU1.C12(value) DU1.D4(value) DU1.D5(value) DU1.D6(value) DU1.E8(value) DU1.E12(value) DU1.F2(value) DU1.G2(value) DU1.G5(value) DU1.G12(value) DU1.H3(value) DU1.H5(value) DU1.H6(value) DU1.H8(value) DU1.H9(value) DU1.H11(value) DU1.H12(value) DU1.J5(value) DU1.J6(value) DU1.J9(value) DU1.J10(value) DU1.K5(value) DU1.K6(value) DU1.K8(value) DU1.K11(value) DU1.K12(value) DU1.L2(value) DU1.L5(value) DU1.L12(value) DU1.M2(value) DU1.N8(value) DU1.N12(value) DU1.P4(value) DU1.P5(value) DU1.P6(value) DU1.R12(value) DU1.U8(value) DU1.U9(value) DU1.U11(value) U1.E7(value) U1.F7(value) U1.J6(value) U1.K6(value) U1.L6(value) U1.M6(value) U1.N6(value) U1.P6(value) U1.R6(value)
VDD-DRAMPLL: DC1.2 DC22.2 DC23.2 DU1.A3(value) DU1.A4(value) DU1.A5(value) DU1.A6(value) DU1.A10(value) DU1.U3(value) DU1.U4(value) DU1.U5(value) DU1.U6(value) DU1.U10(value) U1.N8(value)  [also labelled VDD18-LPDDR]  [project net ALDO2]
SA0: DU1.R2(value) U1.N4(value)
SA1: DU1.P2(value) U1.M5(value)
SA2: DU1.N2(value) U1.M4(value)
SA3: DU1.N3(value) U1.L3(value)
SA4: DU1.M3(value) U1.K3(value)
SA5: DU1.F3(value) U1.J3(value)
SA6: DU1.E3(value) U1.H2(value)
SA7: DU1.E2(value) U1.H3(value)
SA8: DU1.D2(value) U1.G3(value)
SA9: DU1.C2(value) U1.G4(value)
SCK: DR3.2 DU1.J3(value) U1.J1(value)
SCKB: DR3.1 DU1.J2(value) U1.J2(value)
SCKE0: DU1.K3(value) U1.J4(value)
SCKE1: DU1.K4(value) U1.J5(value)
SCS0: DU1.L3(value) U1.K2(value)
SCS1: DU1.L4(value) U1.K4(value)
SDQ0: DU1.P9(value) U1.R2(value)
SDQ1: DU1.N9(value) U1.R1(value)
SDQ2: DU1.N10(value) U1.P2(value)
SDQ3: DU1.N11(value) U1.N3(value)
SDQ4: DU1.M8(value) U1.M1(value)
SDQ5: DU1.M9(value) U1.M2(value)
SDQ6: DU1.M10(value) U1.M3(value)
SDQ7: DU1.M11(value) U1.L2(value)
SDQ8: DU1.R9(value) U1.Y1(value)
SDQ9: DU1.R8(value) U1.W2(value)
SDQ10: DU1.T8(value) U1.W1(value)
SDQ11: DU1.T9(value) U1.V3(value)
SDQ12: DU1.R10(value) U1.U2(value)
SDQ13: DU1.T10(value) U1.T3(value)
SDQ14: DU1.T11(value) U1.T2(value)
SDQ15: DU1.R11(value) U1.T1(value)
SDQ16: DU1.F8(value) U1.E2(value)
SDQ17: DU1.F9(value) U1.D2(value)
SDQ18: DU1.E9(value) U1.D1(value)
SDQ19: DU1.F10(value) U1.D3(value)
SDQ20: DU1.F11(value) U1.A2(value)
SDQ21: DU1.D9(value) U1.B2(value)
SDQ22: DU1.E10(value) U1.B1(value)
SDQ23: DU1.E11(value) U1.A3(value)
SDQ24: DU1.B11(value) U1.A4(value)
SDQ25: DU1.C10(value) U1.B4(value)
SDQ26: DU1.C11(value) U1.C4(value)
SDQ27: DU1.B10(value) U1.B5(value)
SDQ28: DU1.B9(value) U1.C6(value)
SDQ29: DU1.B8(value) U1.A7(value)
SDQ30: DU1.C8(value) U1.B8(value)
SDQ31: DU1.C9(value) U1.B7(value)
SDQM0: DU1.L8(value) U1.R3(value)
SDQM1: DU1.P8(value) U1.Y2(value)
SDQM2: DU1.G8(value) U1.F3(value)
SDQM3: DU1.D8(value) U1.B3(value)
SDQS0: DU1.L10(value) U1.N1(value)
SDQS0B: DU1.L11(value) U1.N2(value)
SDQS1: DU1.P10(value) U1.V1(value)
SDQS1B: DU1.P11(value) U1.V2(value)
SDQS2: DU1.G10(value) U1.C1(value)
SDQS2B: DU1.G11(value) U1.C2(value)
SDQS3: DU1.D10(value) U1.B6(value)
SDQS3B: DU1.D11(value) U1.A6(value)
SODT0: DU1.J8(value) U1.E3(value)
SVREF: DC7.2 DC8.1 DC9.2 DC20.2 DC21.2 DR1.1 DR7.2 DU1.H4(value) DU1.J11(value) U1.K1(value)
NetDR2_2: DR2.2 DU1.B3(value)
NetDR4_2: DR4.2 DU1.B4(value)
NetDR5_1: DR5.1 U1.T5(value)

Not connected (* = marked no-connect by the designer): DU1 A1(value) A2(value) A12(value) A13(value) B1(value) B13(value) C4(value) K9(value) R3(value) T1(value) T13(value) U1(value) U2(value) U12(value) U13(value); U1 C5(value) D4(value) D6(value) D7(value) E6(value) F1(value) F2(value) F4(value) G1(value) G2(value) G5(value) P3(value) R4(value) R5(value) T4(value) U3(value) V4(value)

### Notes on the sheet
- LPDDR3_32X1

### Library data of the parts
DC1 DC7-DC17 DC20-DC23 = CAPACITOR_0_Dup2: PAGE: 1
DC2-DC6 = CAPACITOR_0_Dup3: PAGE: 2
DR1 DR3 DR7 = ?_0
DR2 DR4 = R1 0805
DR5 = R_Dup2
DU1 = LPDDR3_FBGA178_0: SWAP_INFO: (S1+S2); SPLIT_INST: TRUE
U1 = A83_0

## Sheet 03 POWER TREE.SchDoc
size 420 x 297 mm
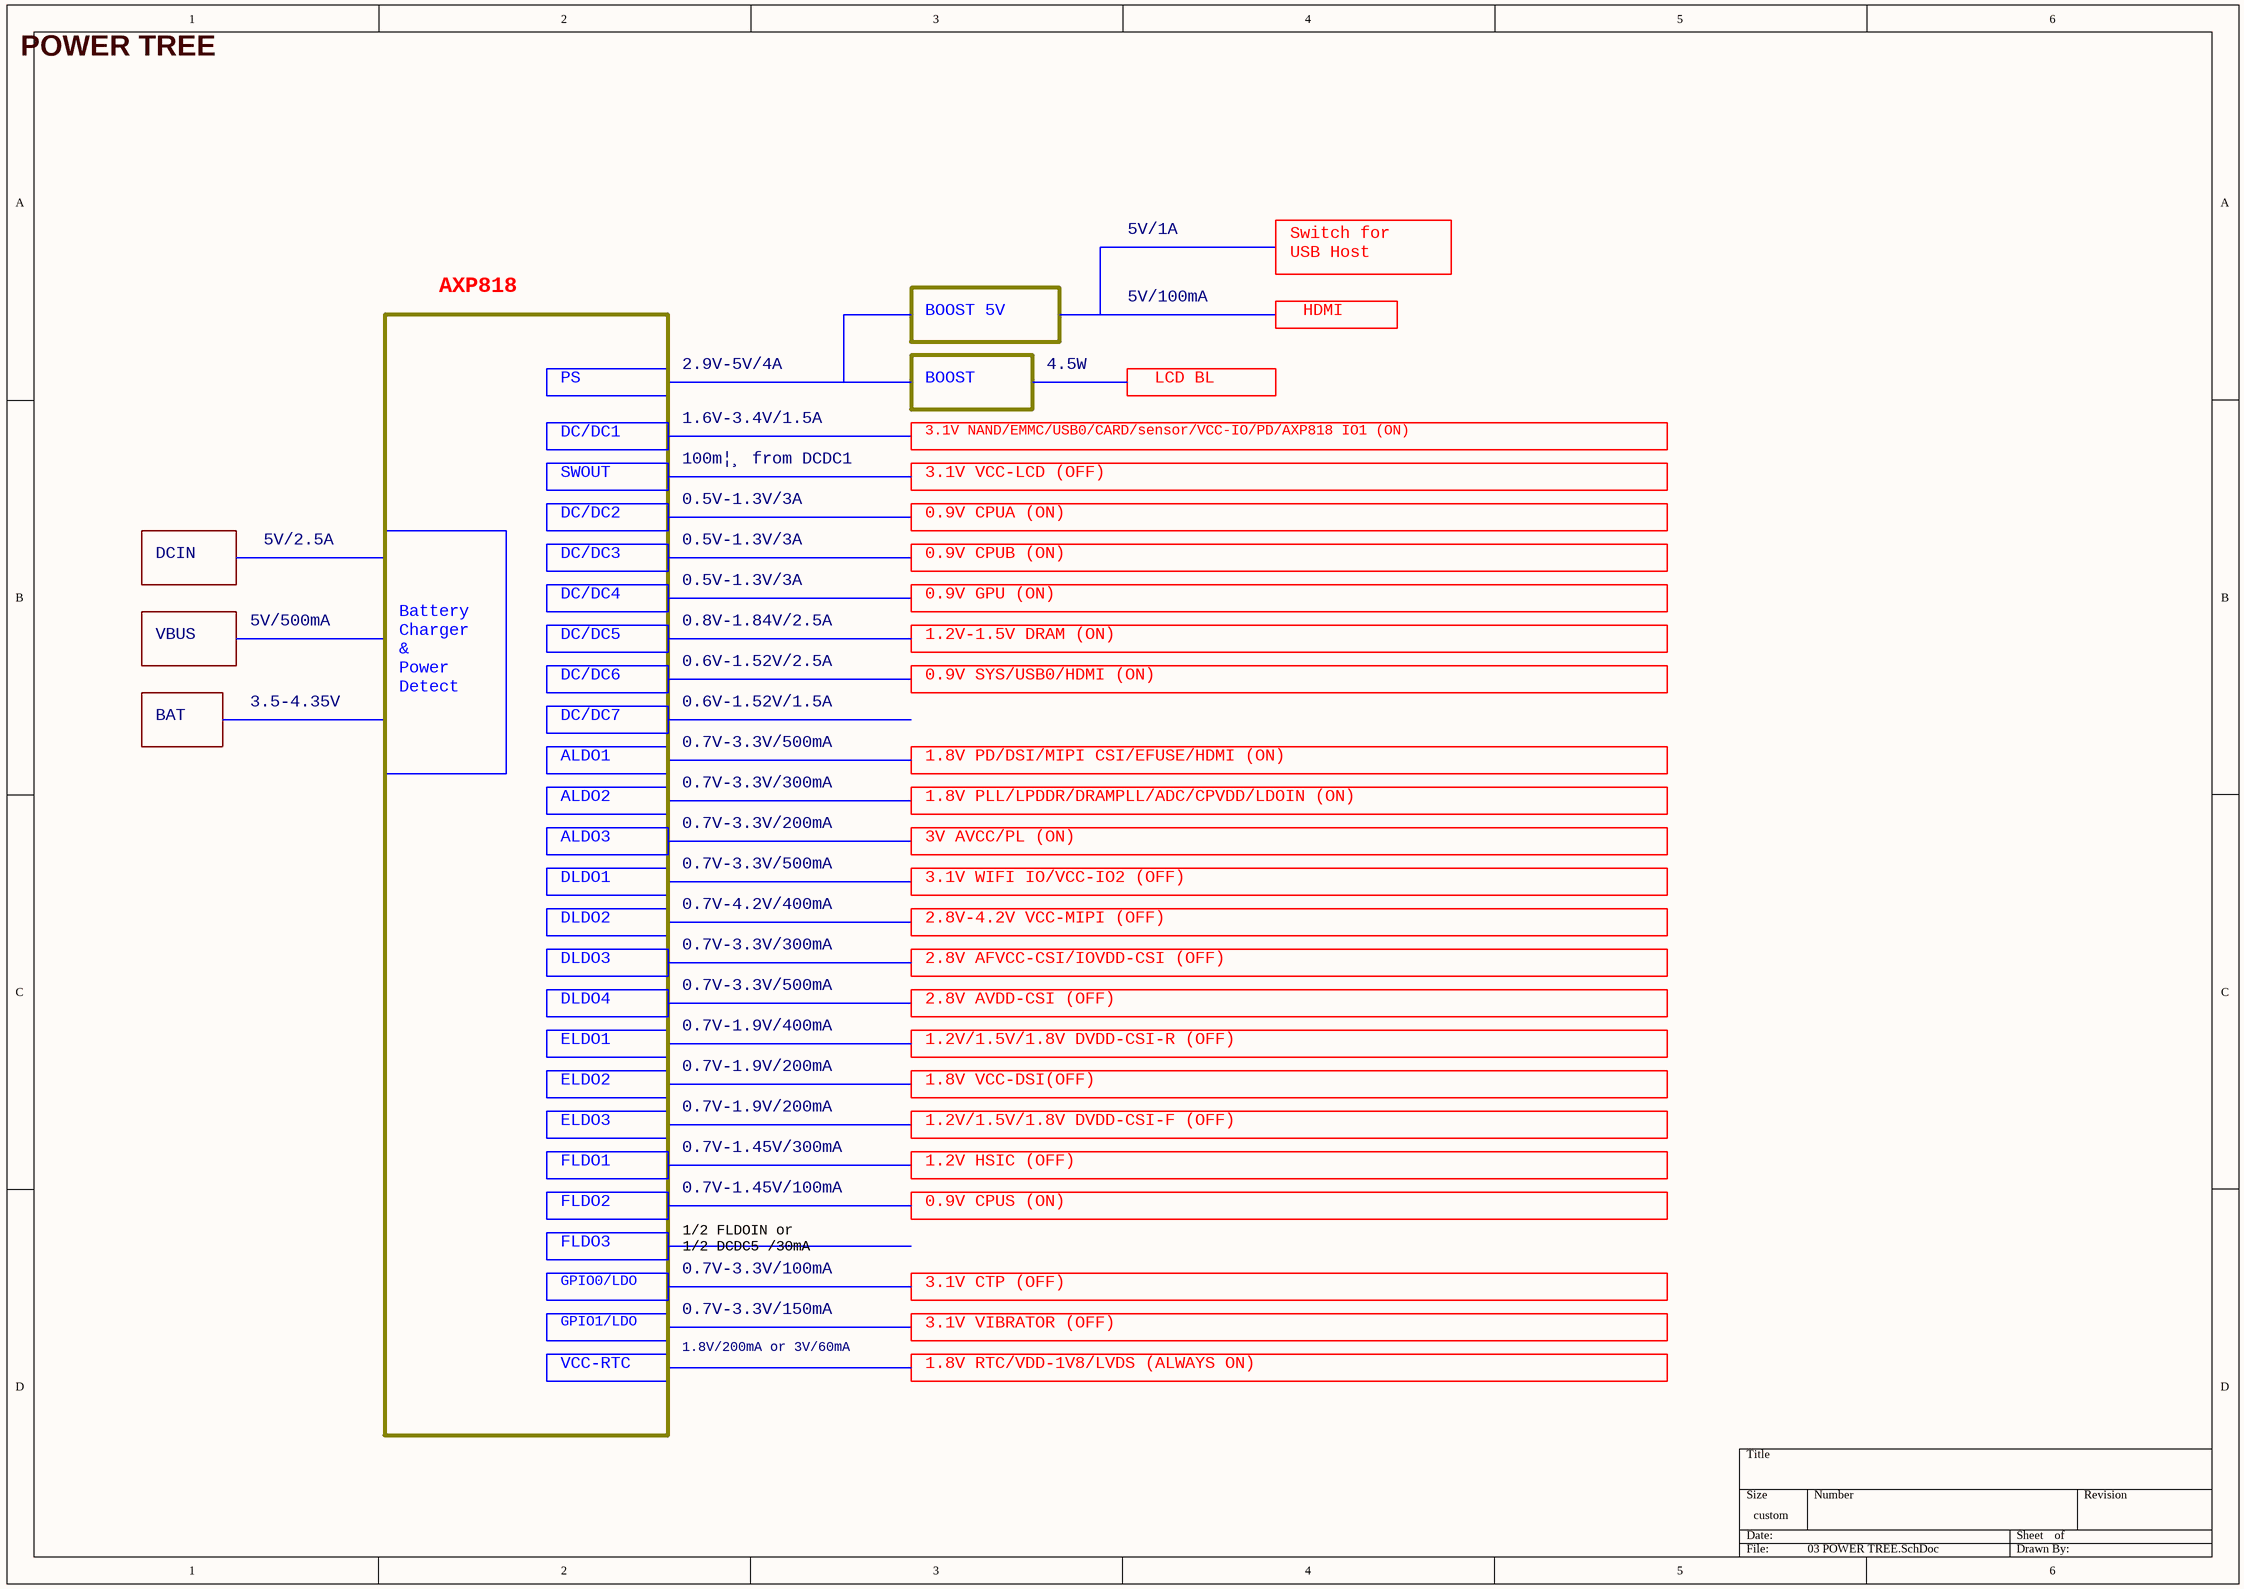
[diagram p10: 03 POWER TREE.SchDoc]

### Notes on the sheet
- POWER TREE
- 5V/1A
- Switch for
  USB Host
- AXP818
- BOOST 5V
- 5V/100mA
- HDMI
- PS
- 2.9V-5V/4A
- BOOST
- 4.5W
- LCD BL
- DC/DC1
- 100m¦¸ from DCDC1
- 1.6V-3.4V/1.5A
- 3.1V NAND/EMMC/USB0/CARD/sensor/VCC-IO/PD/AXP818 IO1 (ON)
- SWOUT
- DC/DC2
- 0.5V-1.3V/3A
- 0.9V CPUA (ON)
- 3.1V VCC-LCD (OFF)
- DCIN
- 5V/2.5A
- Battery
  Charger
  &
  Power
  Detect
- DC/DC3
- DC/DC4
- 0.9V CPUB (ON)
- 0.9V GPU (ON)
- VBUS
- 5V/500mA
- DC/DC5
- 0.8V-1.84V/2.5A
- 0.6V-1.52V/2.5A
- 1.2V-1.5V DRAM (ON)
- BAT
- 3.5-4.35V
- DC/DC6
- DC/DC7
- 0.6V-1.52V/1.5A
- 0.9V SYS/USB0/HDMI (ON)
- ALDO1
- ALDO2
- 0.7V-3.3V/500mA
- 0.7V-3.3V/300mA
- 1.8V PD/DSI/MIPI CSI/EFUSE/HDMI (ON)
- 1.8V PLL/LPDDR/DRAMPLL/ADC/CPVDD/LDOIN (ON)
- ALDO3
- 0.7V-3.3V/200mA
- 3V AVCC/PL (ON)
- DLDO1
- DLDO2
- 0.7V-4.2V/400mA
- 2.8V-4.2V VCC-MIPI (OFF)
- 3.1V WIFI IO/VCC-IO2 (OFF)
- DLDO3
- DLDO4
- 2.8V AVDD-CSI (OFF)
- 2.8V AFVCC-CSI/IOVDD-CSI (OFF)
- ELDO1
- 0.7V-1.9V/400mA
- 0.7V-1.9V/200mA
- 1.2V/1.5V/1.8V DVDD-CSI-R (OFF)
- ELDO2
- ELDO3
- 1.2V/1.5V/1.8V DVDD-CSI-F (OFF)
- 1.8V VCC-DSI(OFF)
- FLDO1
- FLDO2
- 0.7V-1.45V/300mA
- 0.7V-1.45V/100mA
- 1.2V HSIC (OFF)
- 0.9V CPUS (ON)
- FLDO3
- 1/2 FLDOIN or
  1/2 DCDC5 /30mA
- 0.7V-3.3V/100mA
- GPIO1/LDO
- GPIO0/LDO
- 0.7V-3.3V/150mA
- 3.1V CTP (OFF)
- 3.1V VIBRATOR (OFF)
- VCC-RTC
- 1.8V/200mA or 3V/60mA
- 1.8V RTC/VDD-1V8/LVDS (ALWAYS ON)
